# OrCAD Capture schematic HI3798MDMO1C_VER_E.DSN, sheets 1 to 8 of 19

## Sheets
1 SHEET_01
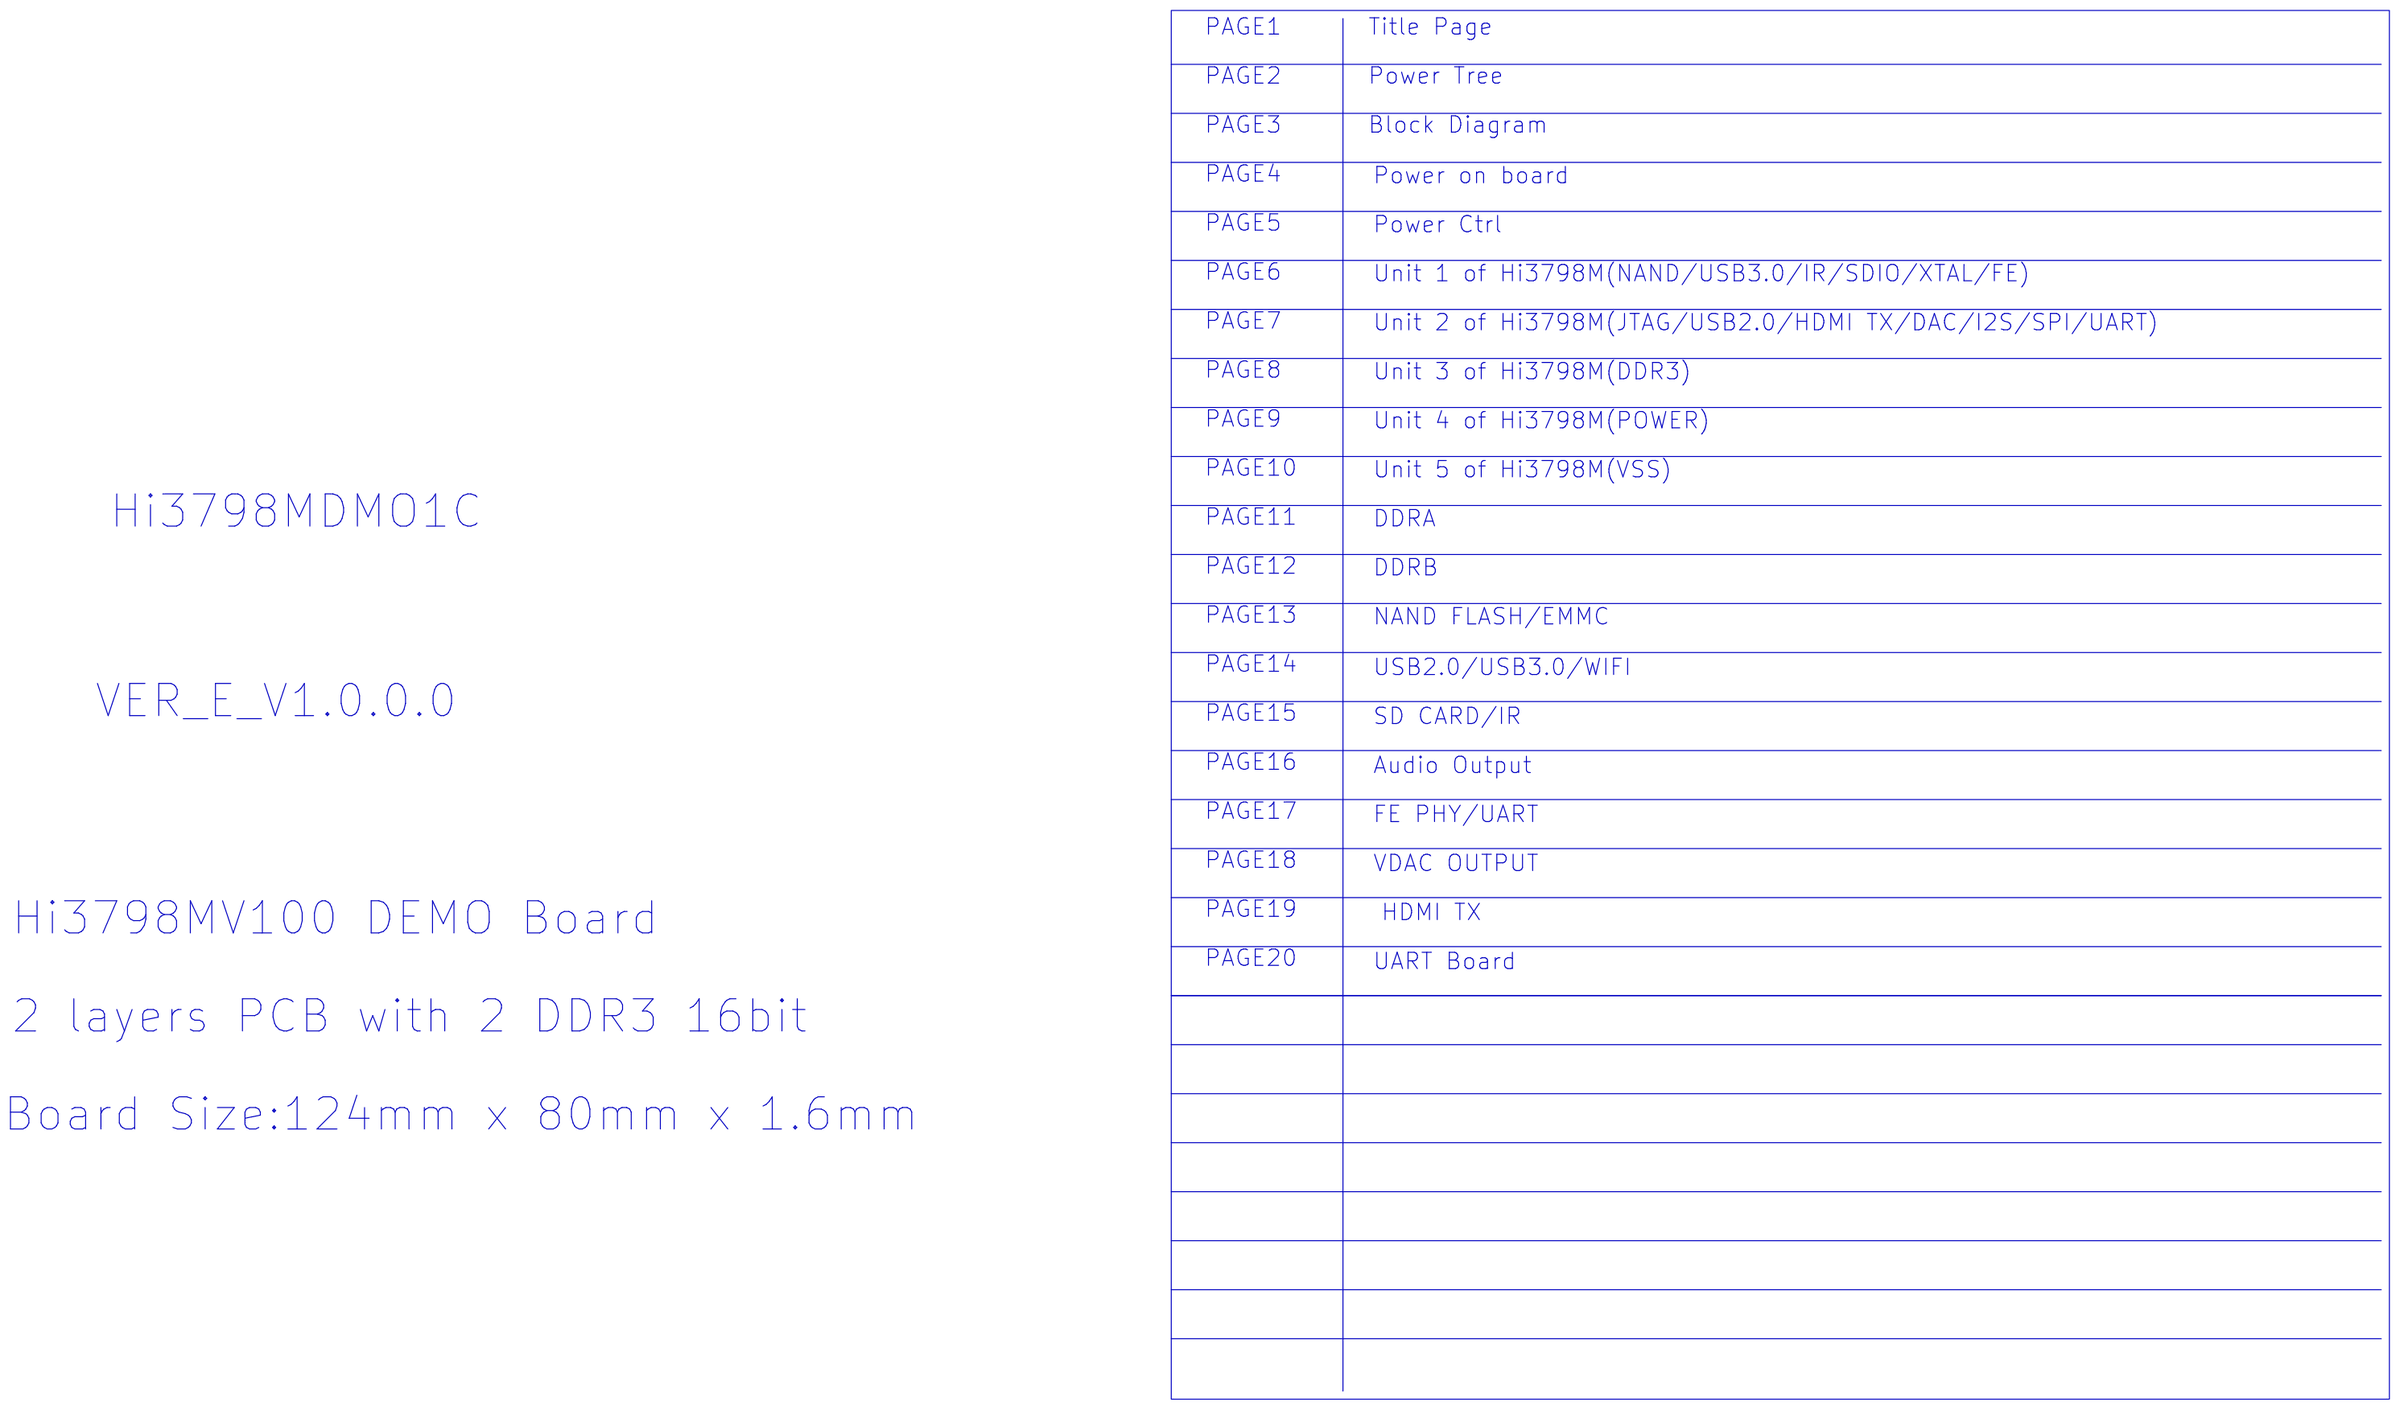
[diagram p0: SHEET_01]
2 SHEET_02
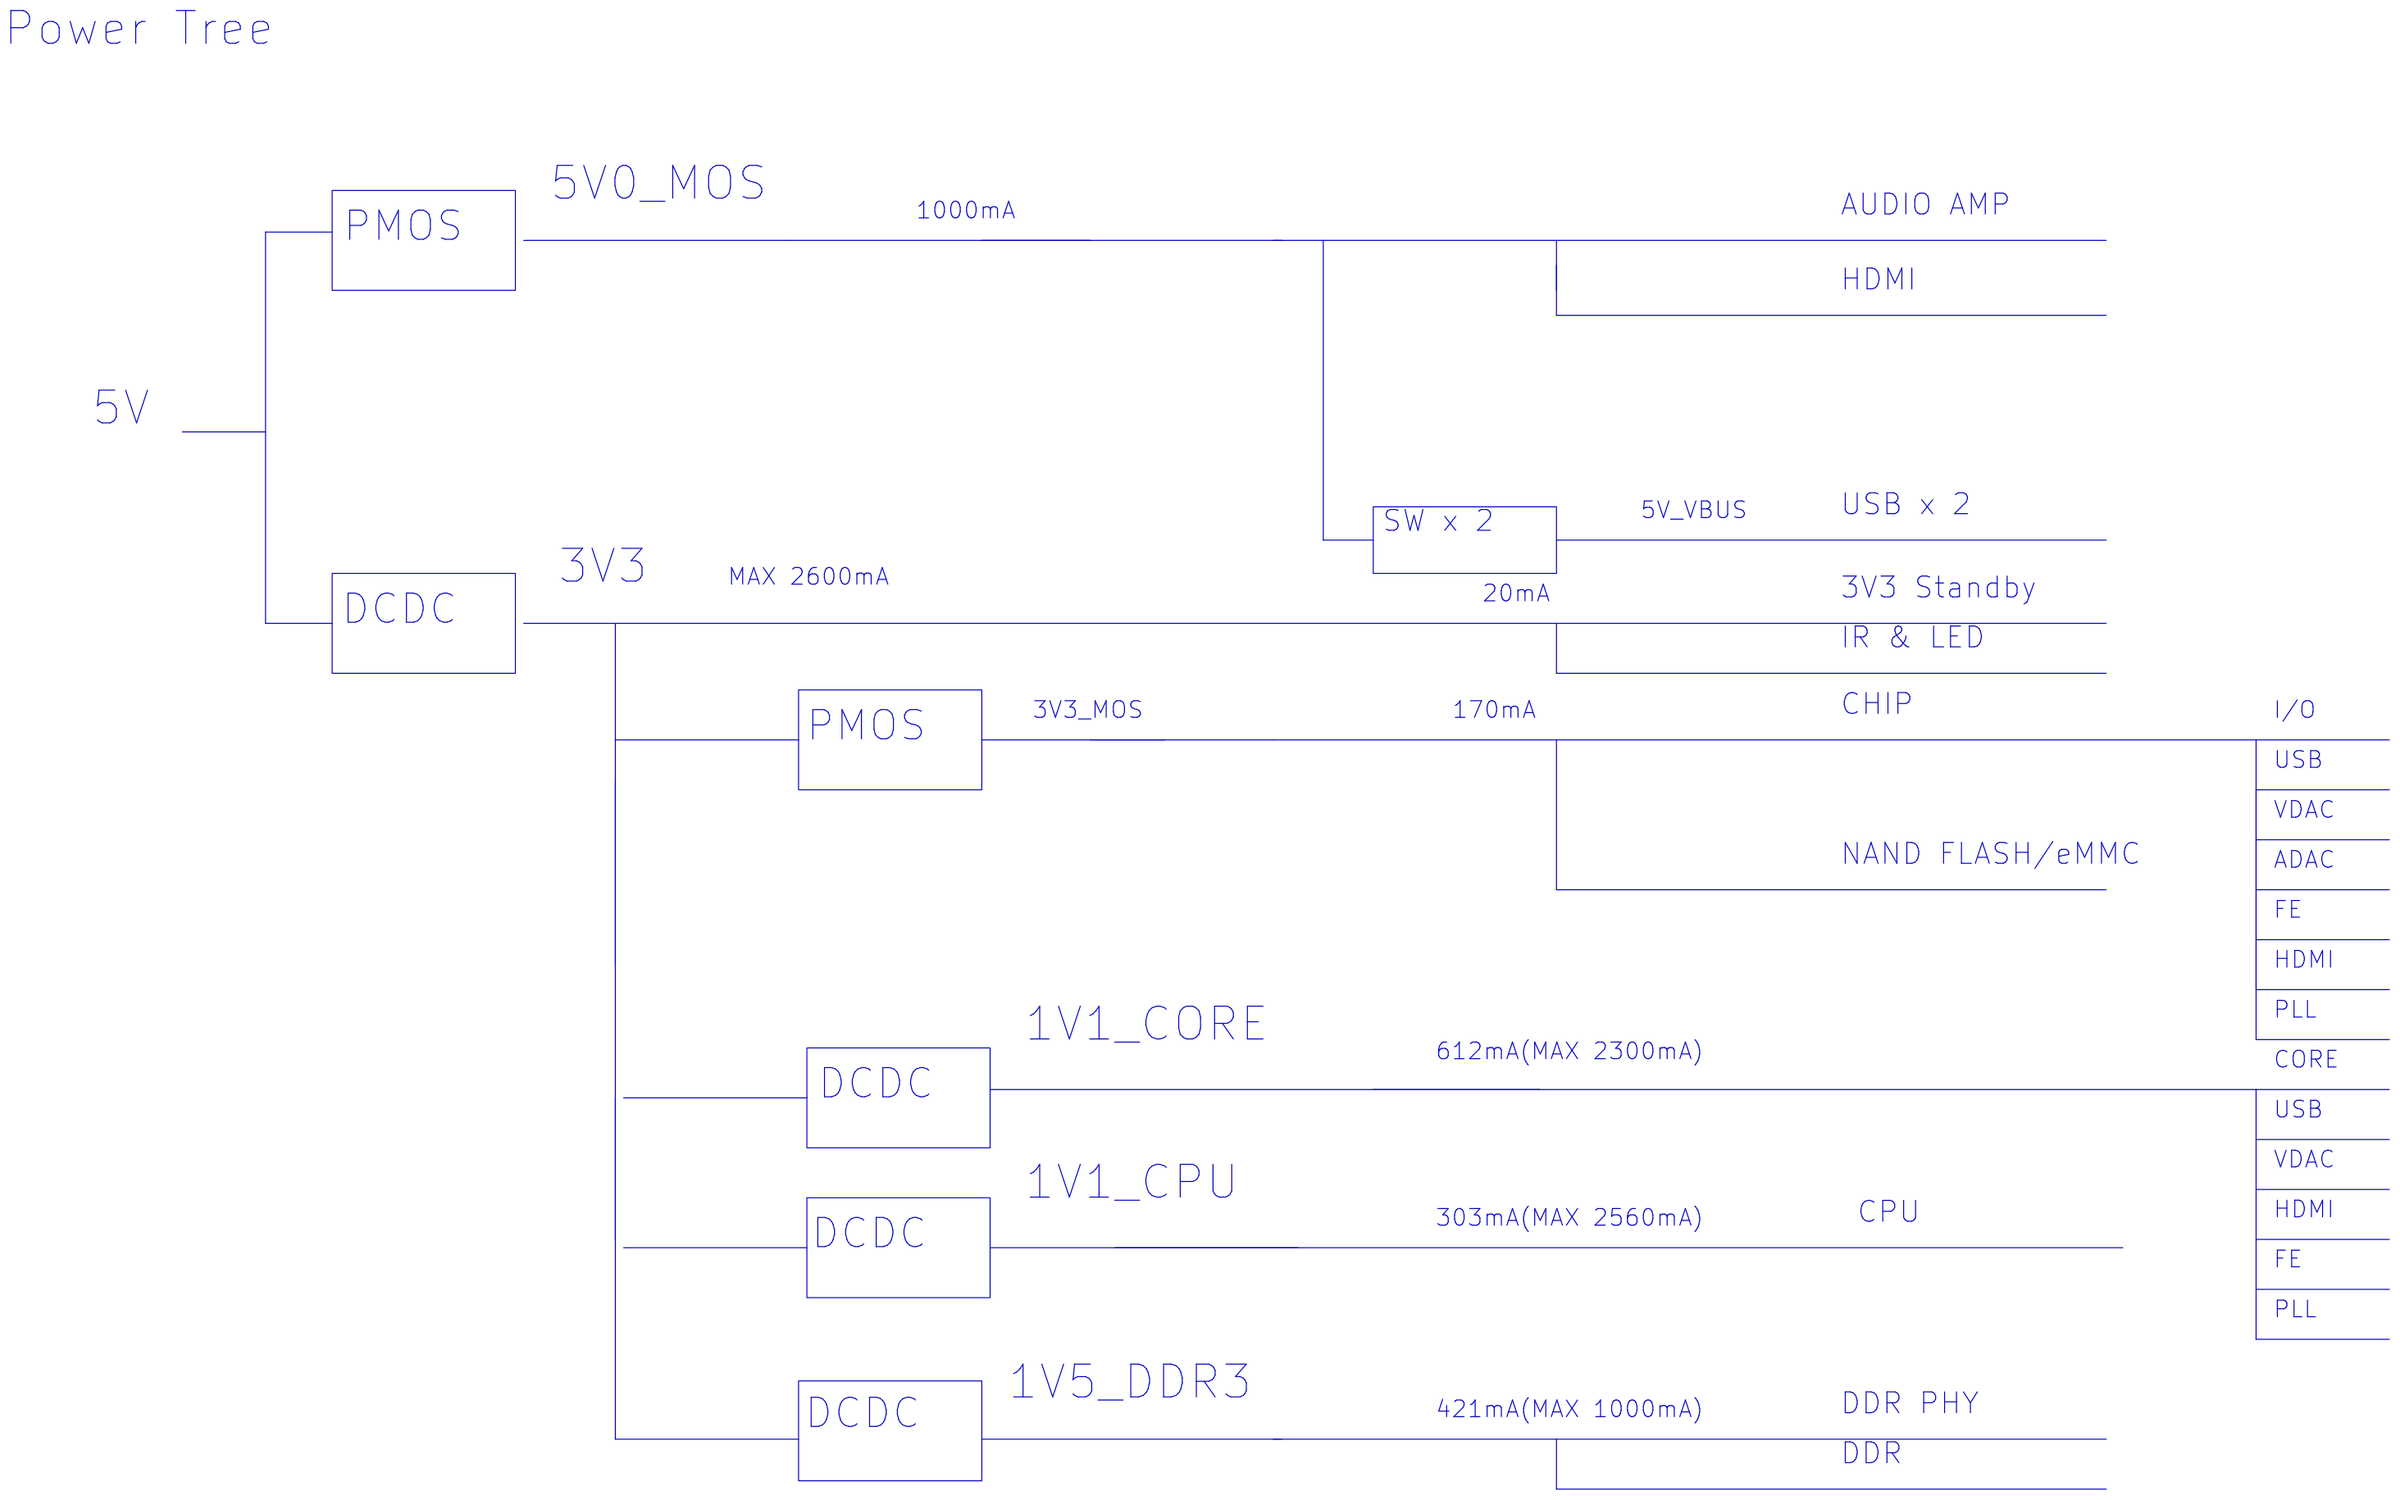
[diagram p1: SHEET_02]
3 SHEET_03: size Custom
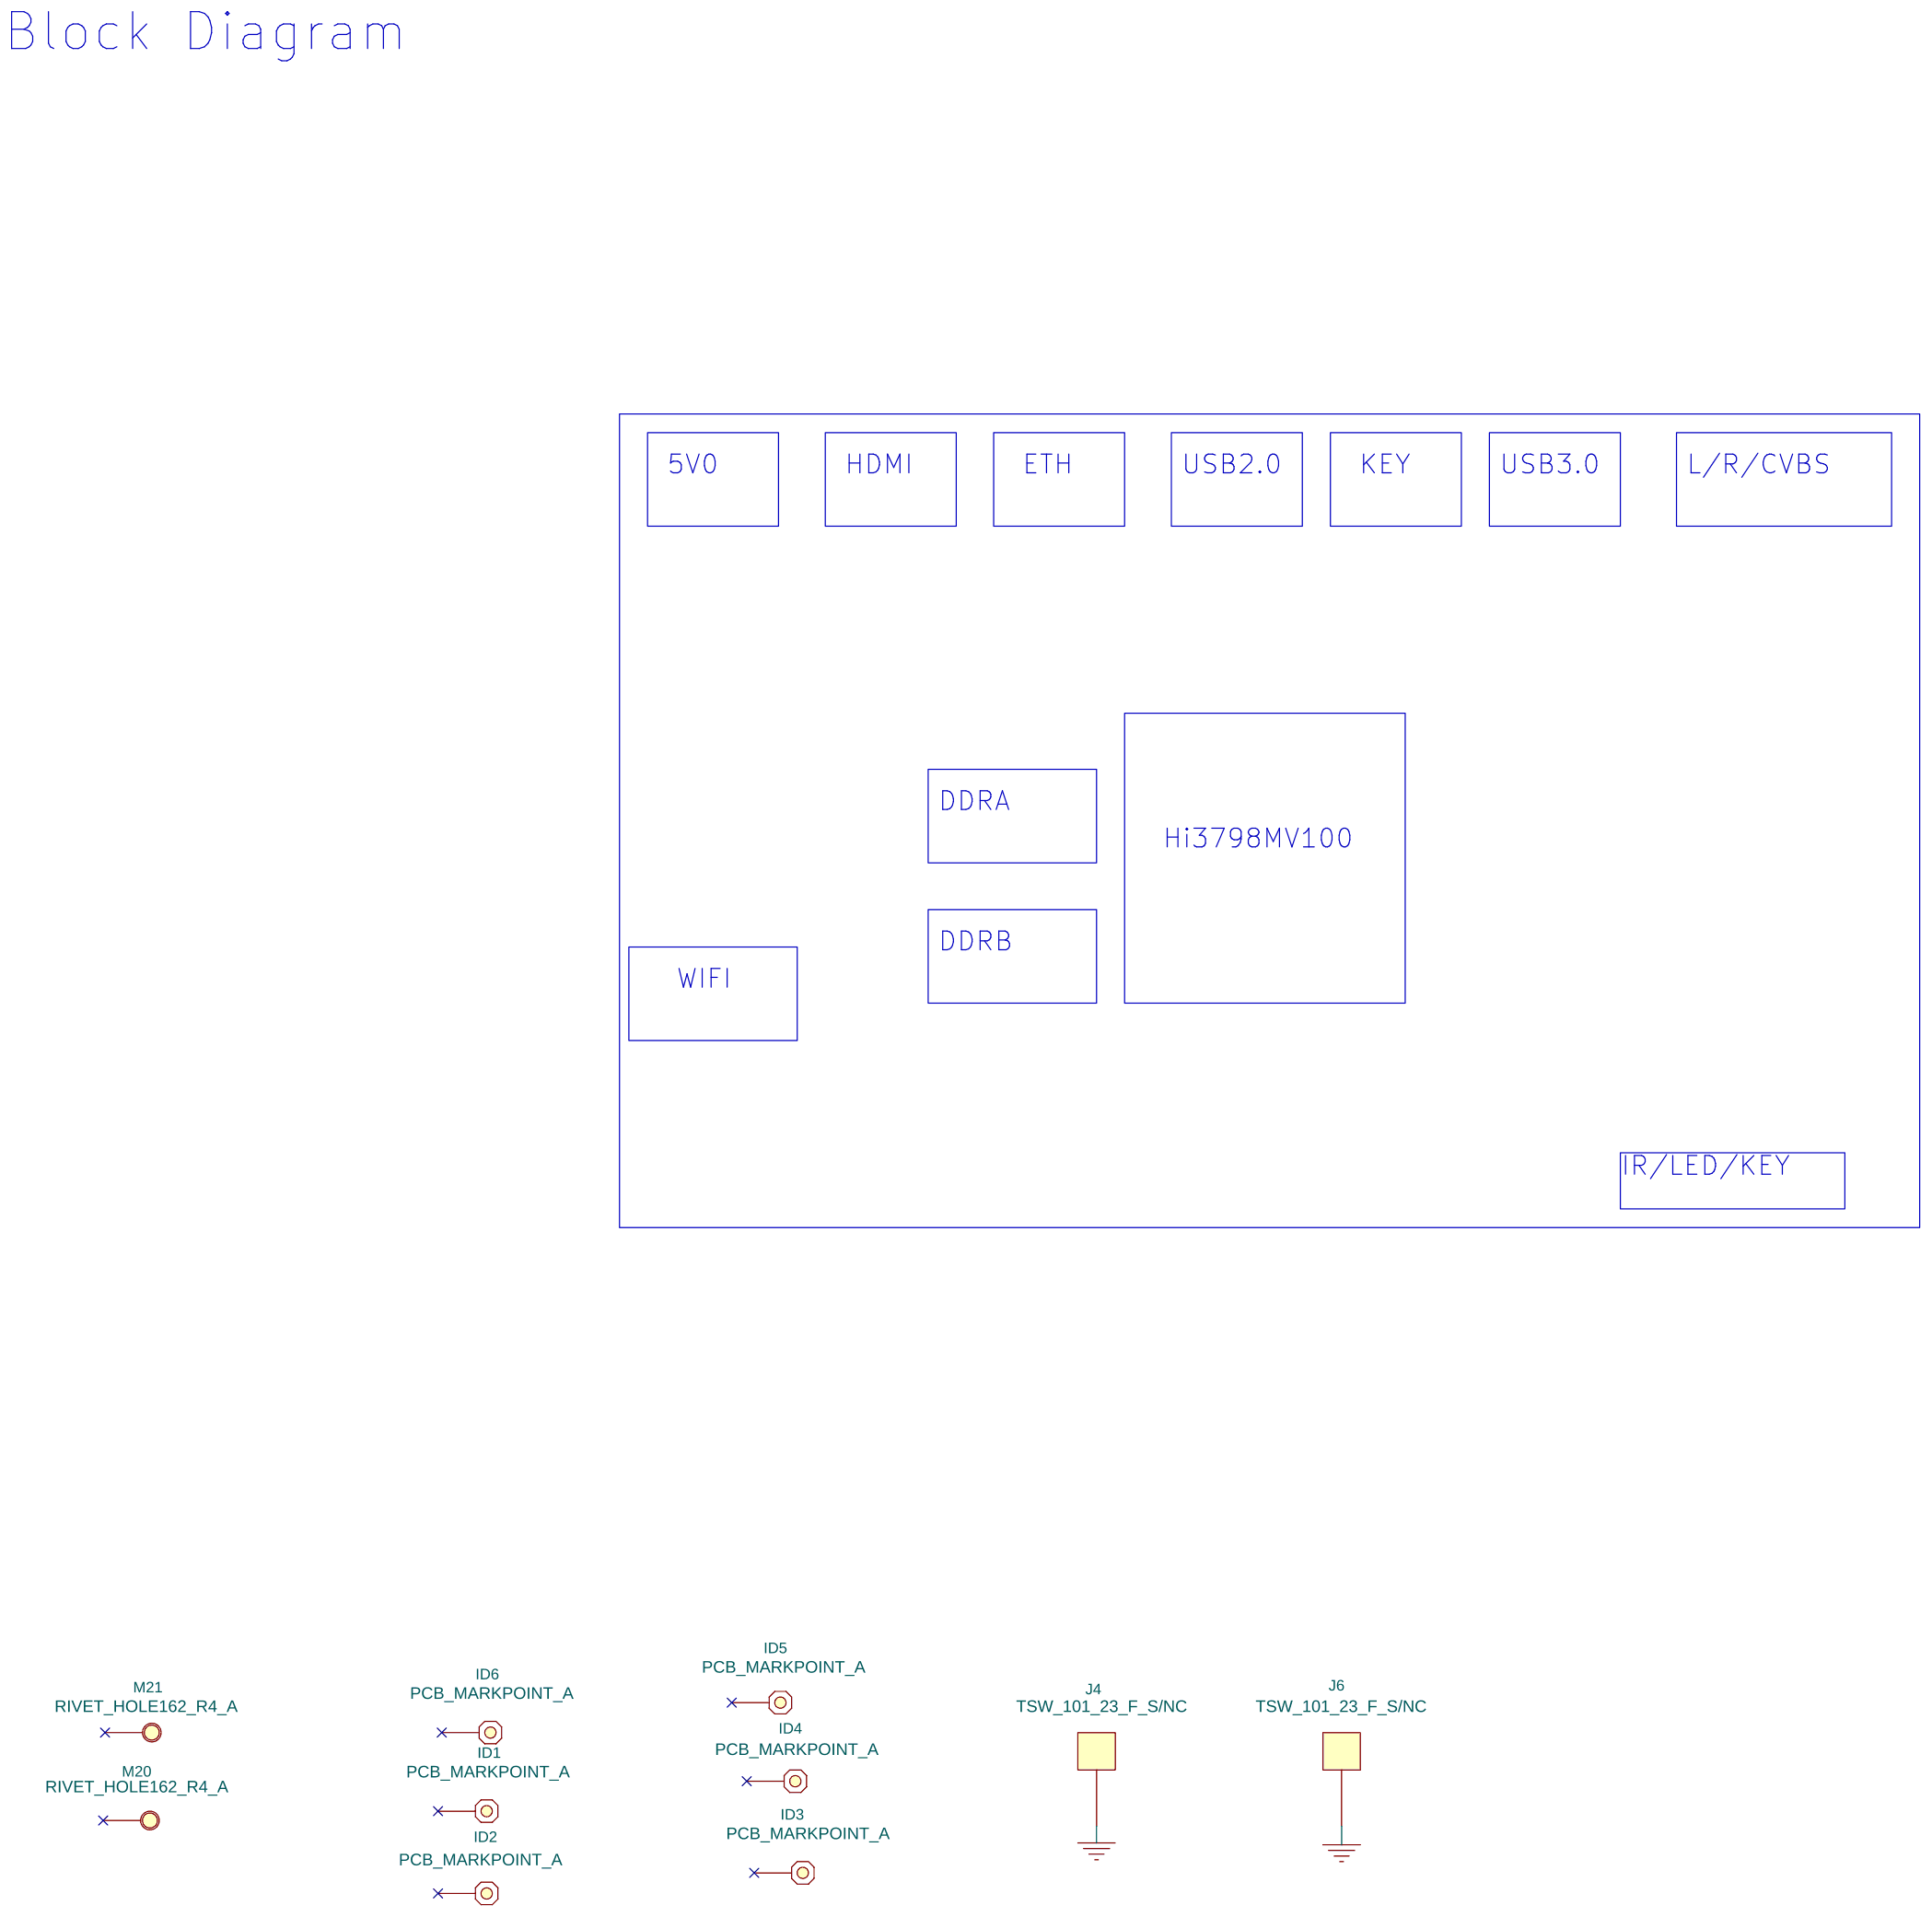
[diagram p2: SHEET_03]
4 SHEET_04: size Custom
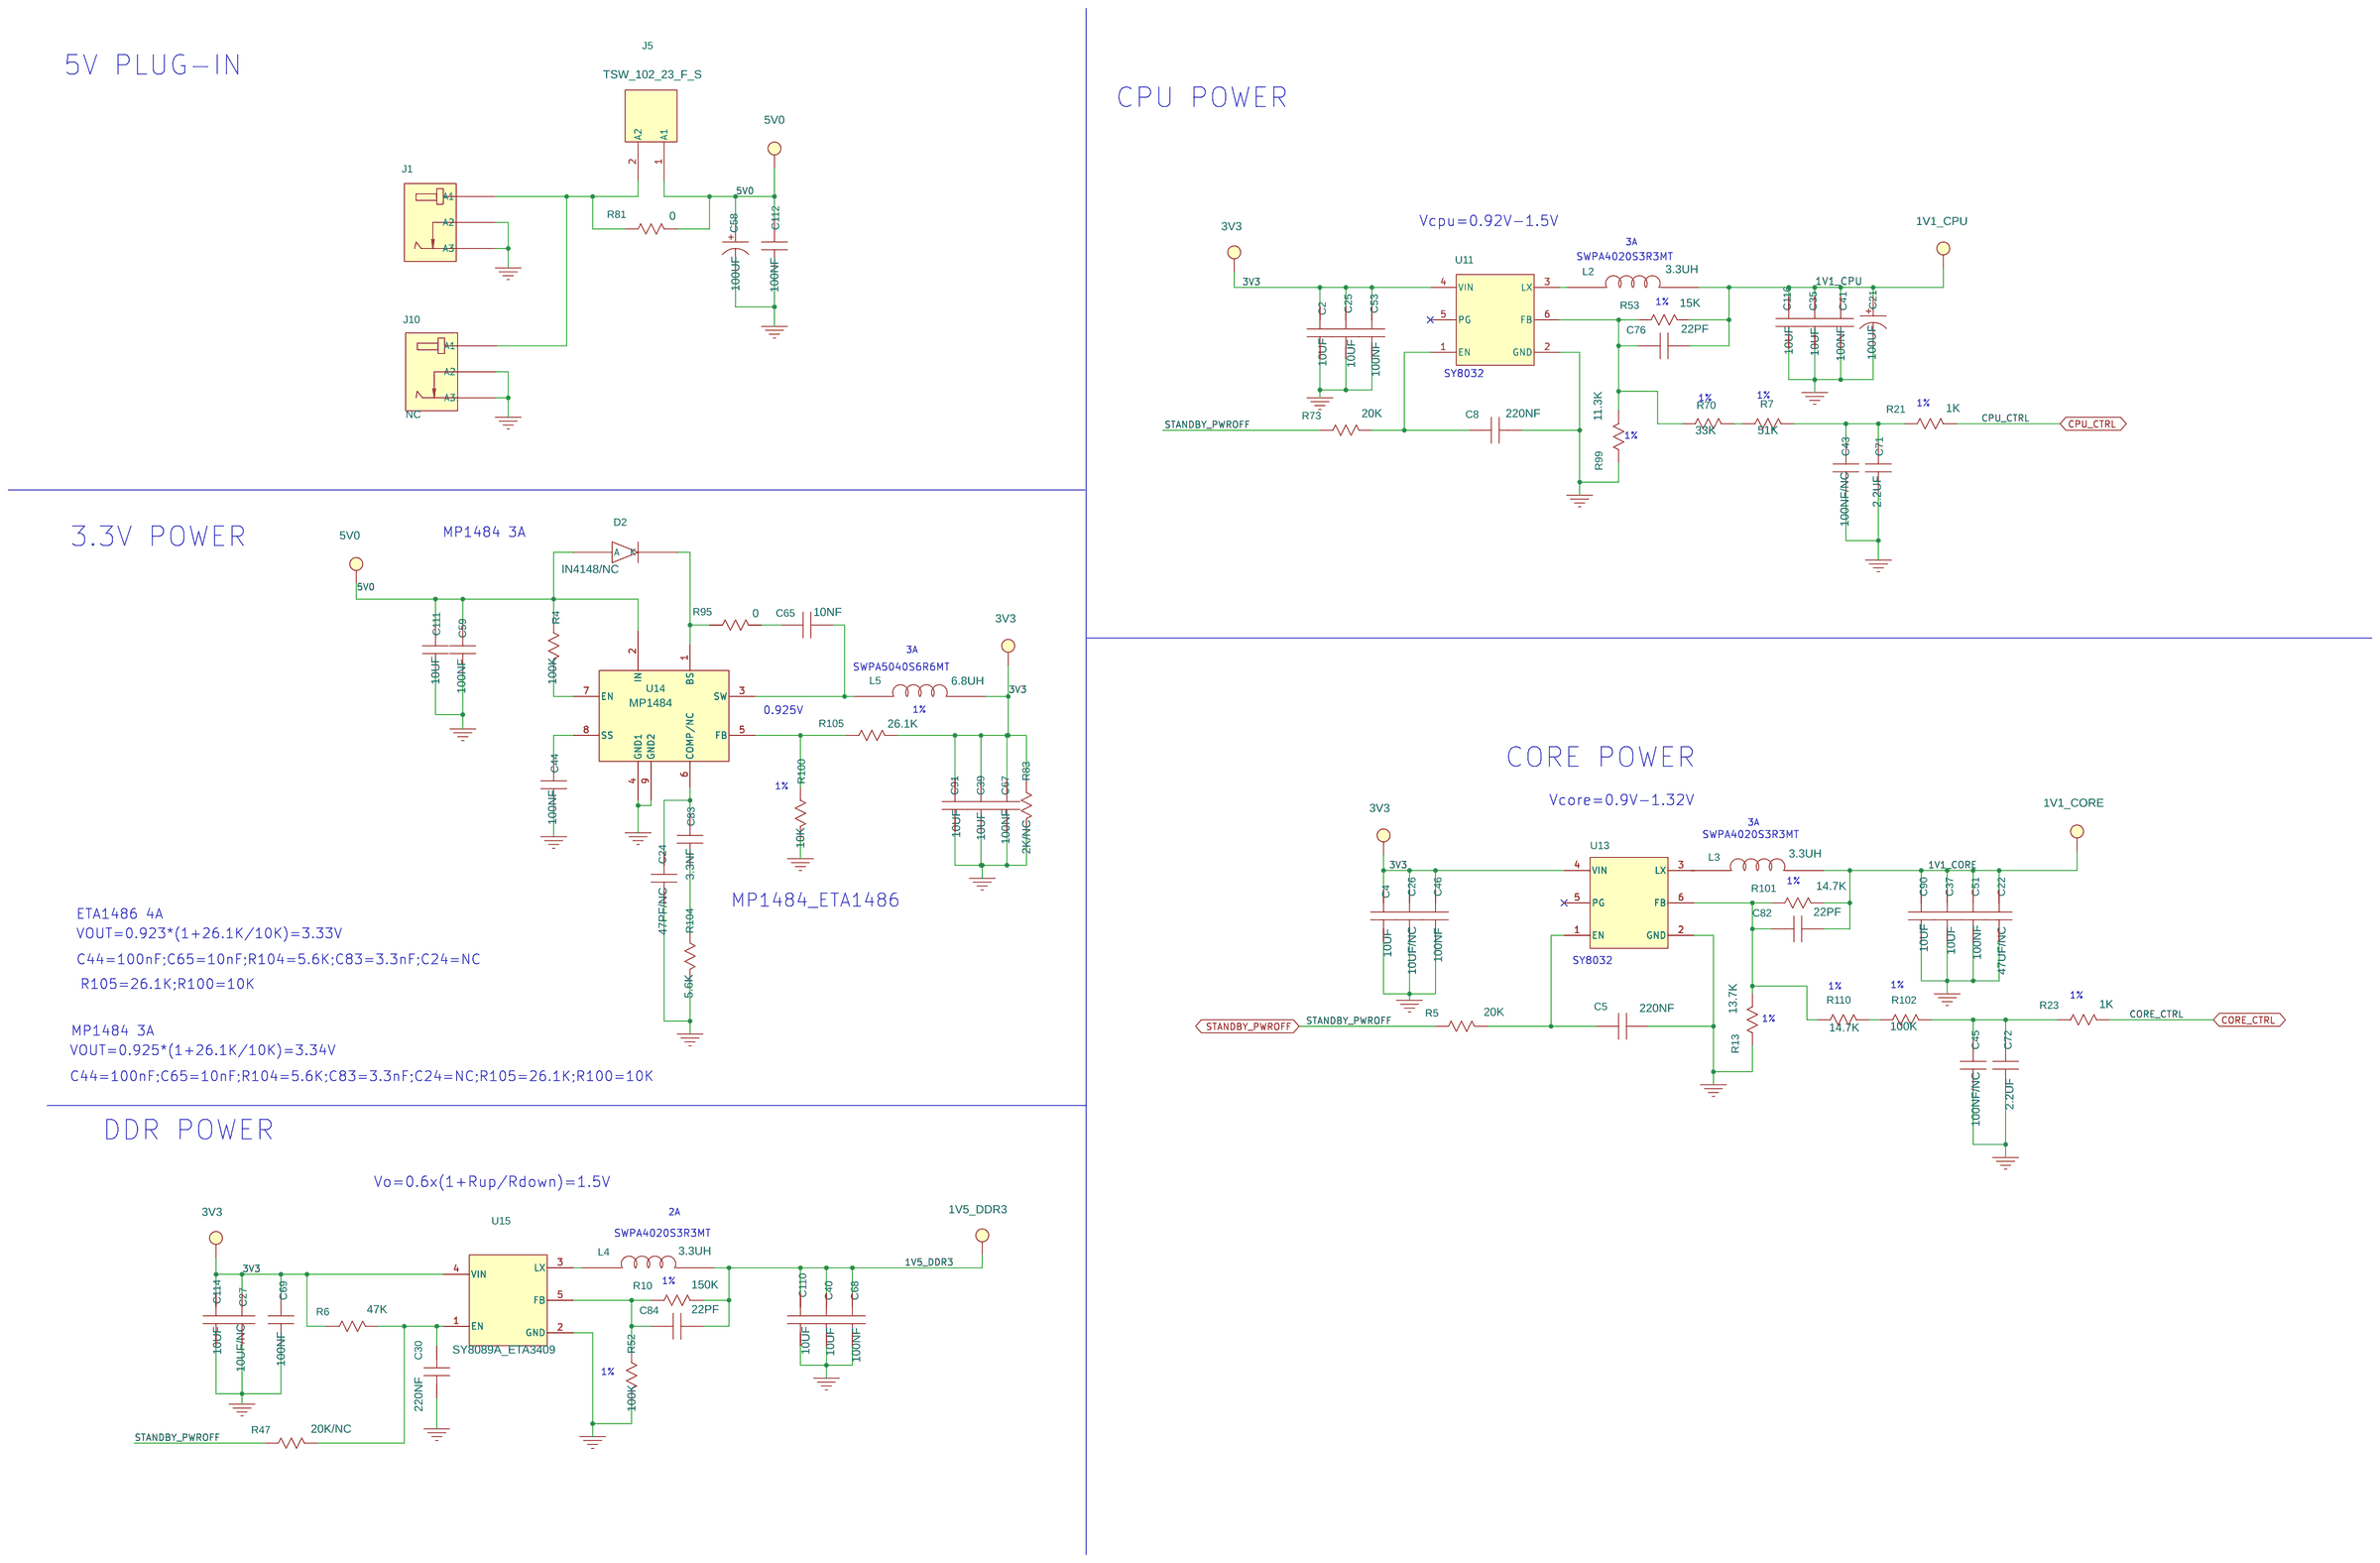
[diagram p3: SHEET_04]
5 SHEET_05: size A
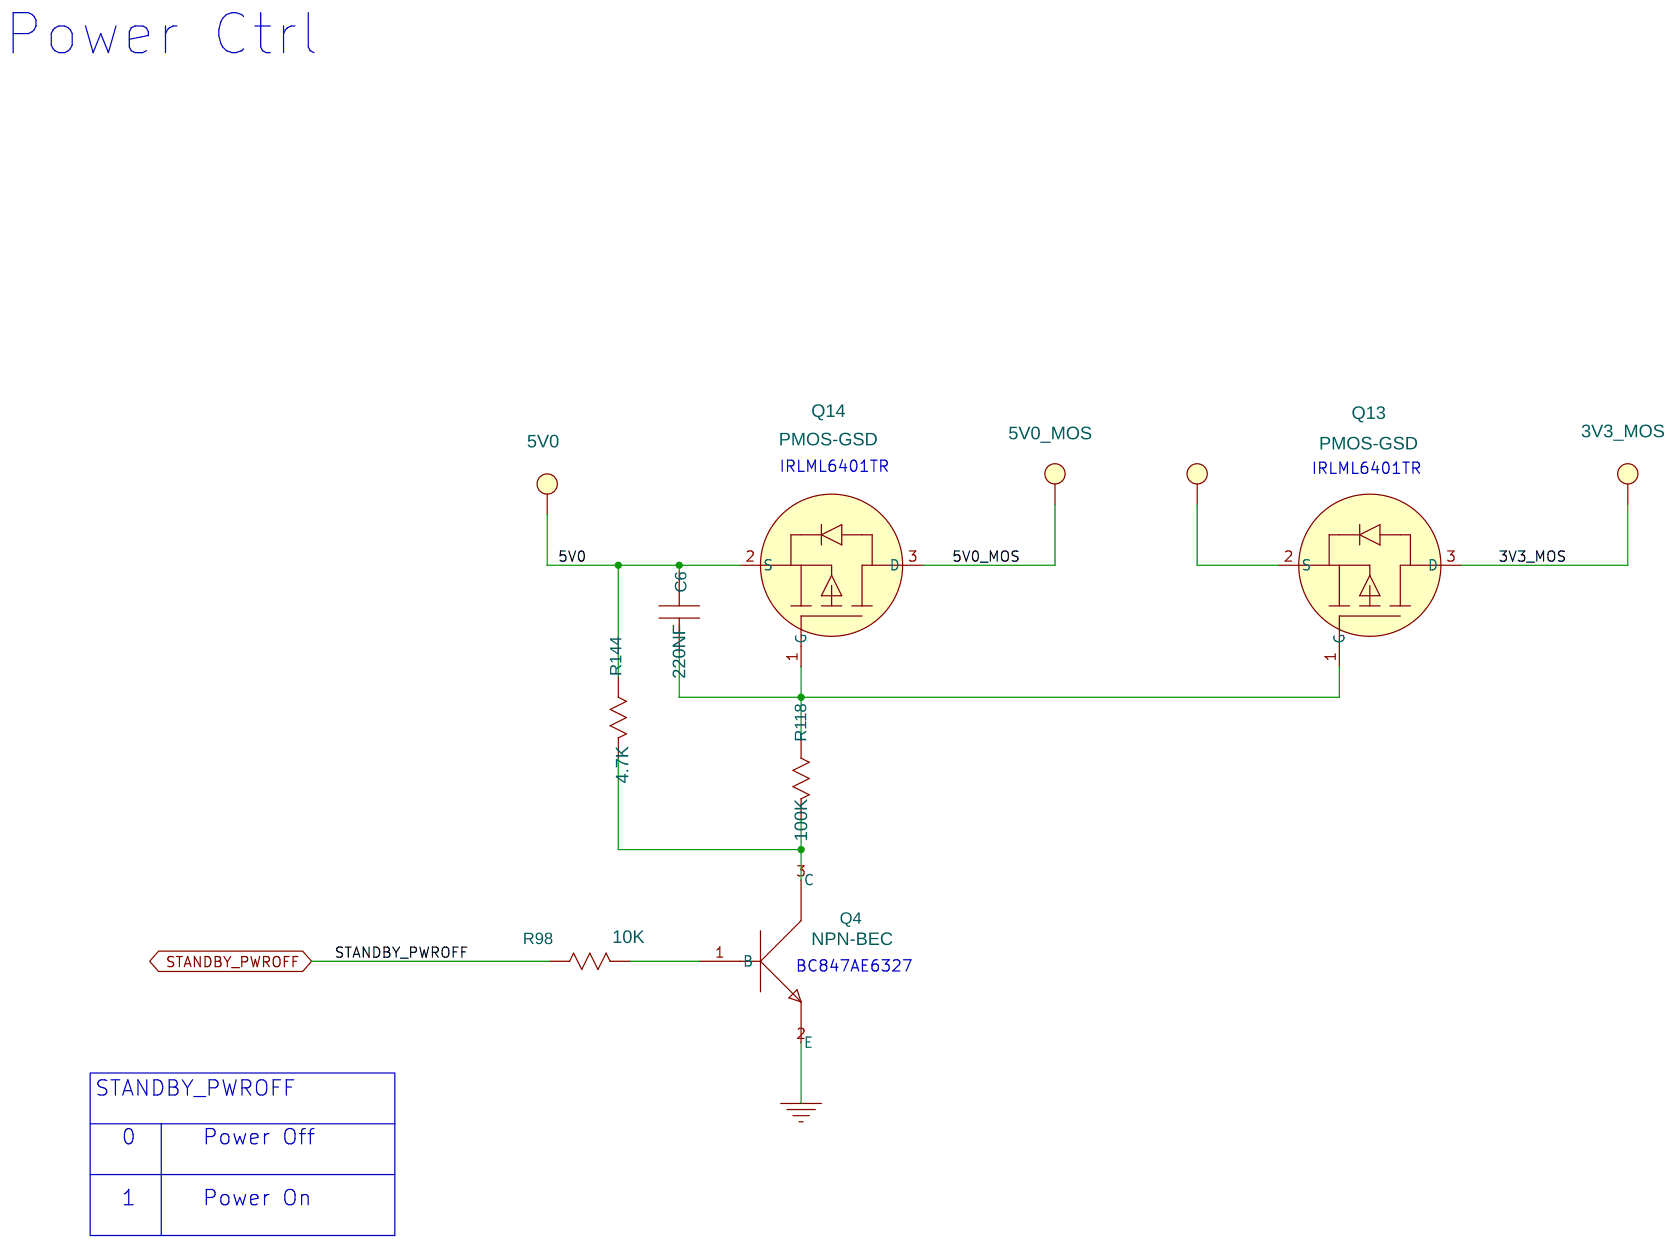
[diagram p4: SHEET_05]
6 SHEET_06: size Custom
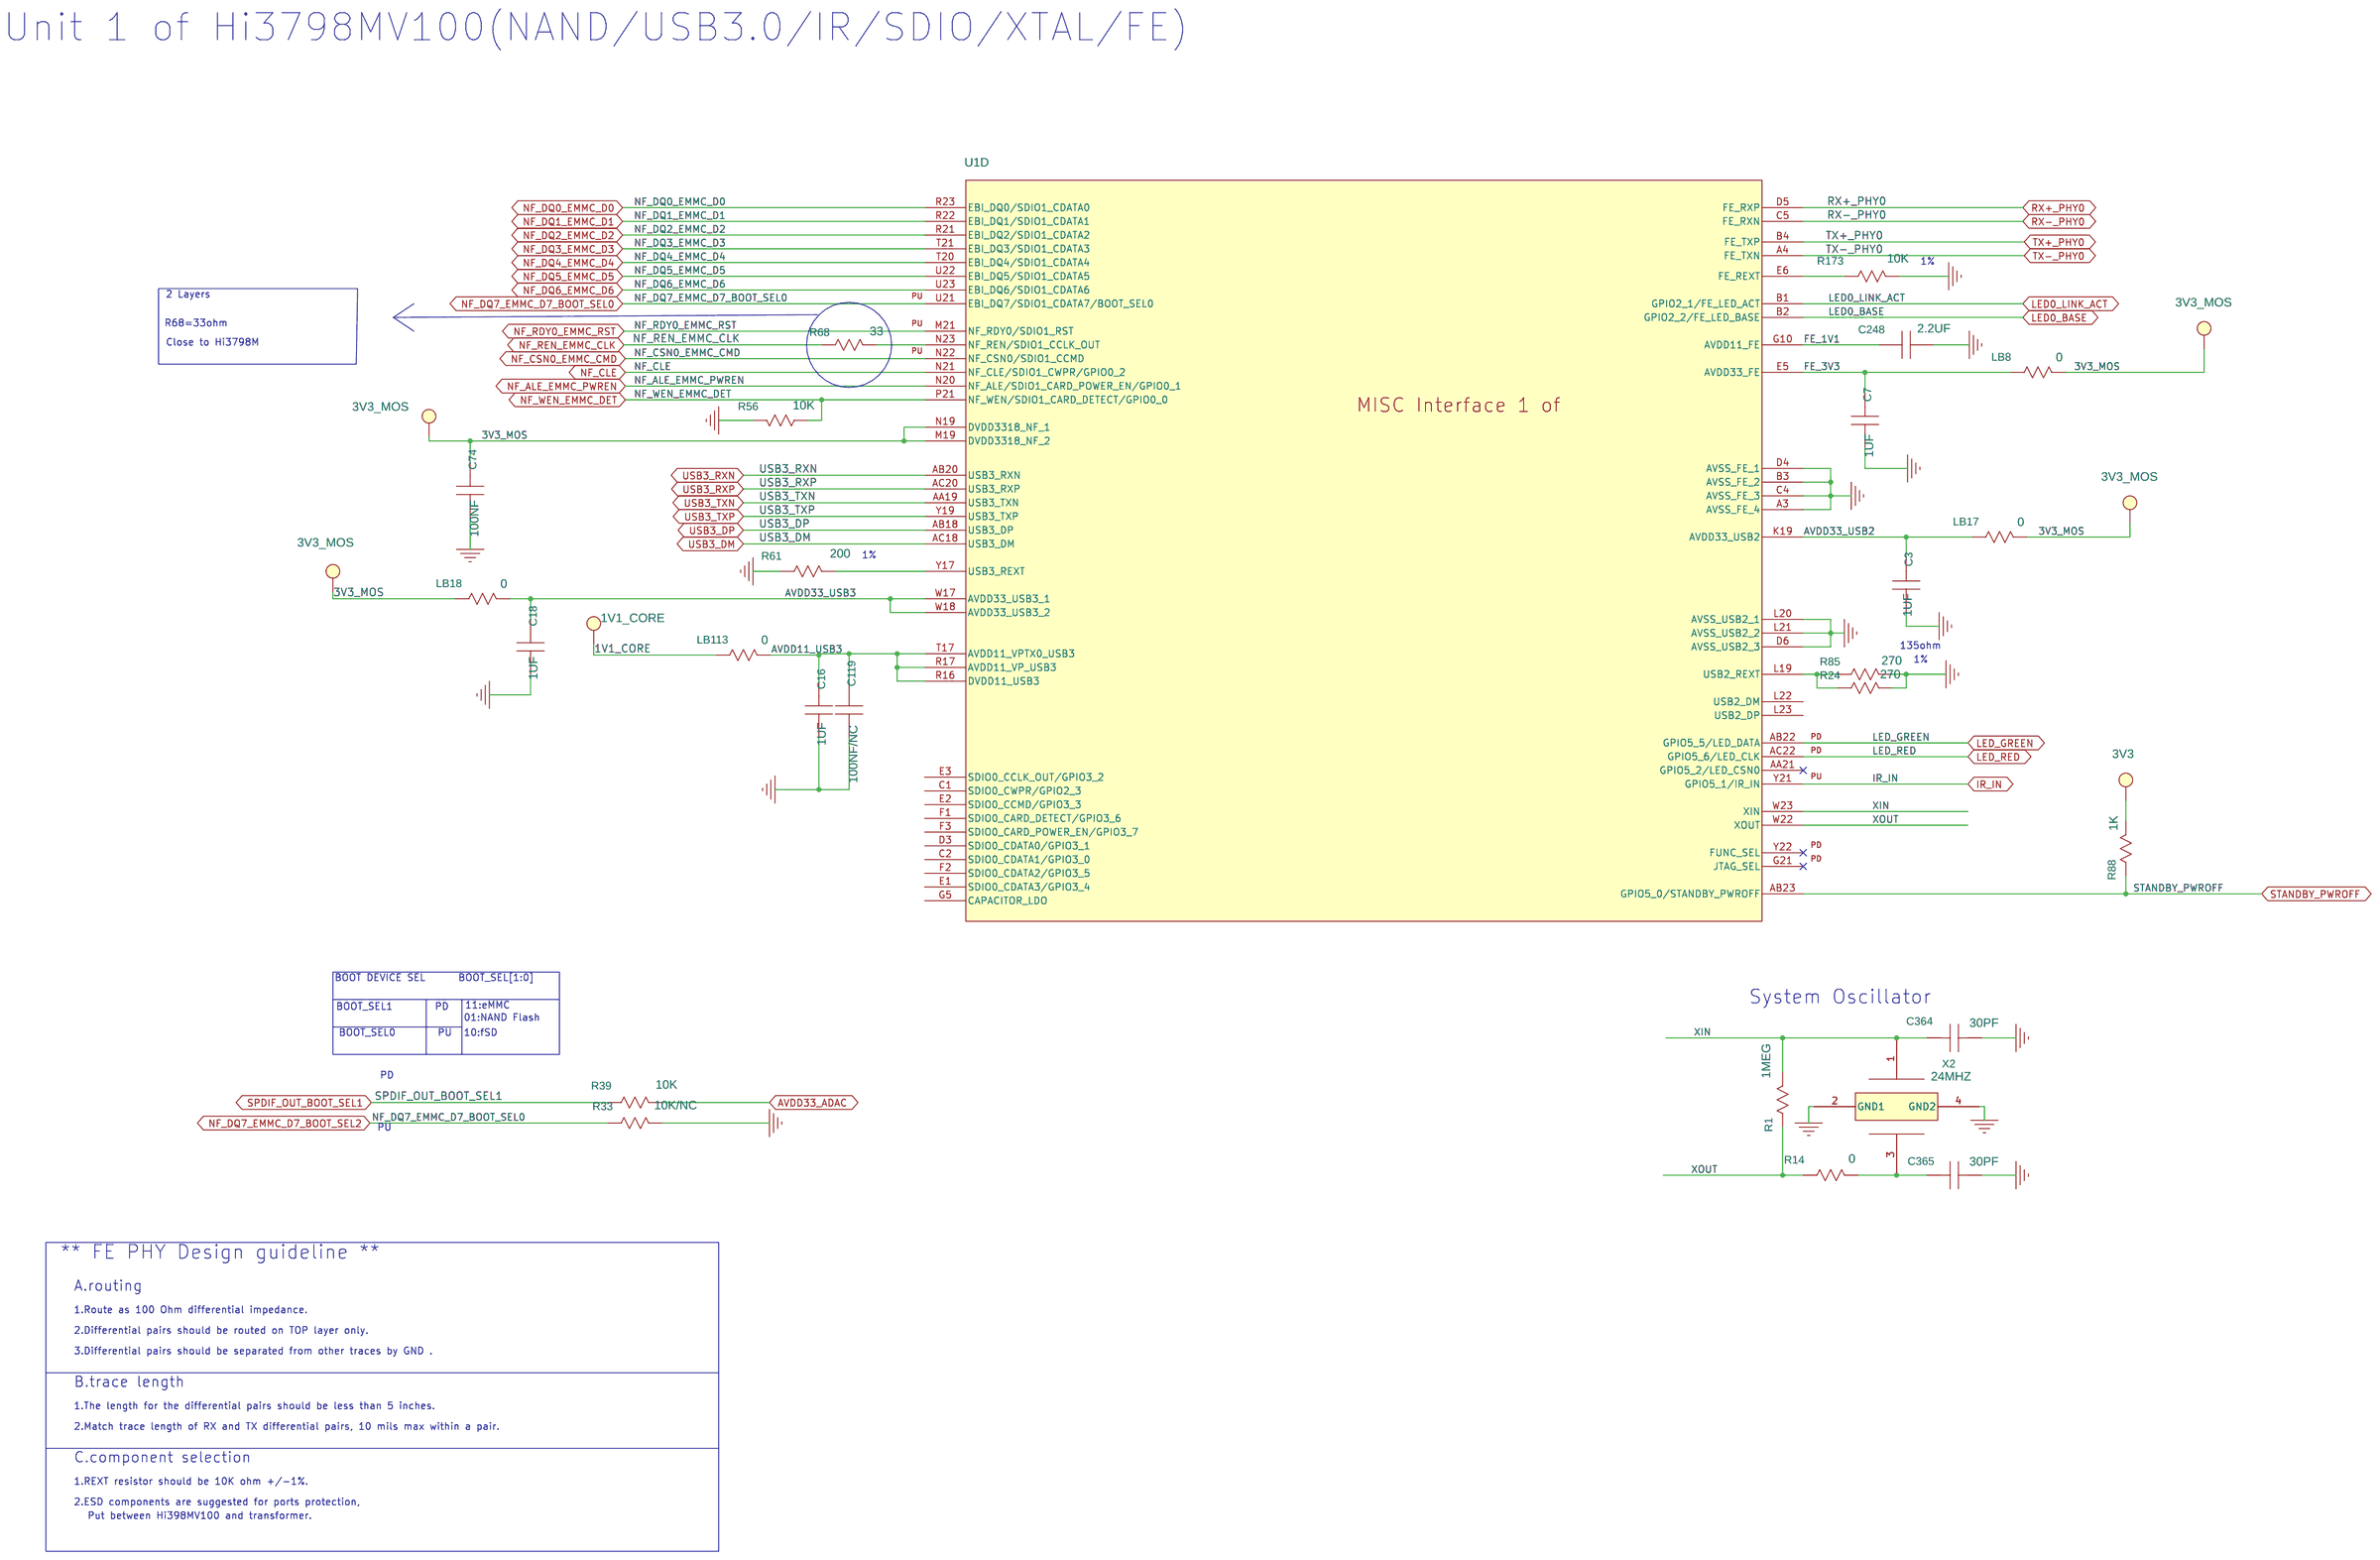
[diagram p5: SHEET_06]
7 SHEET_07: size Custom
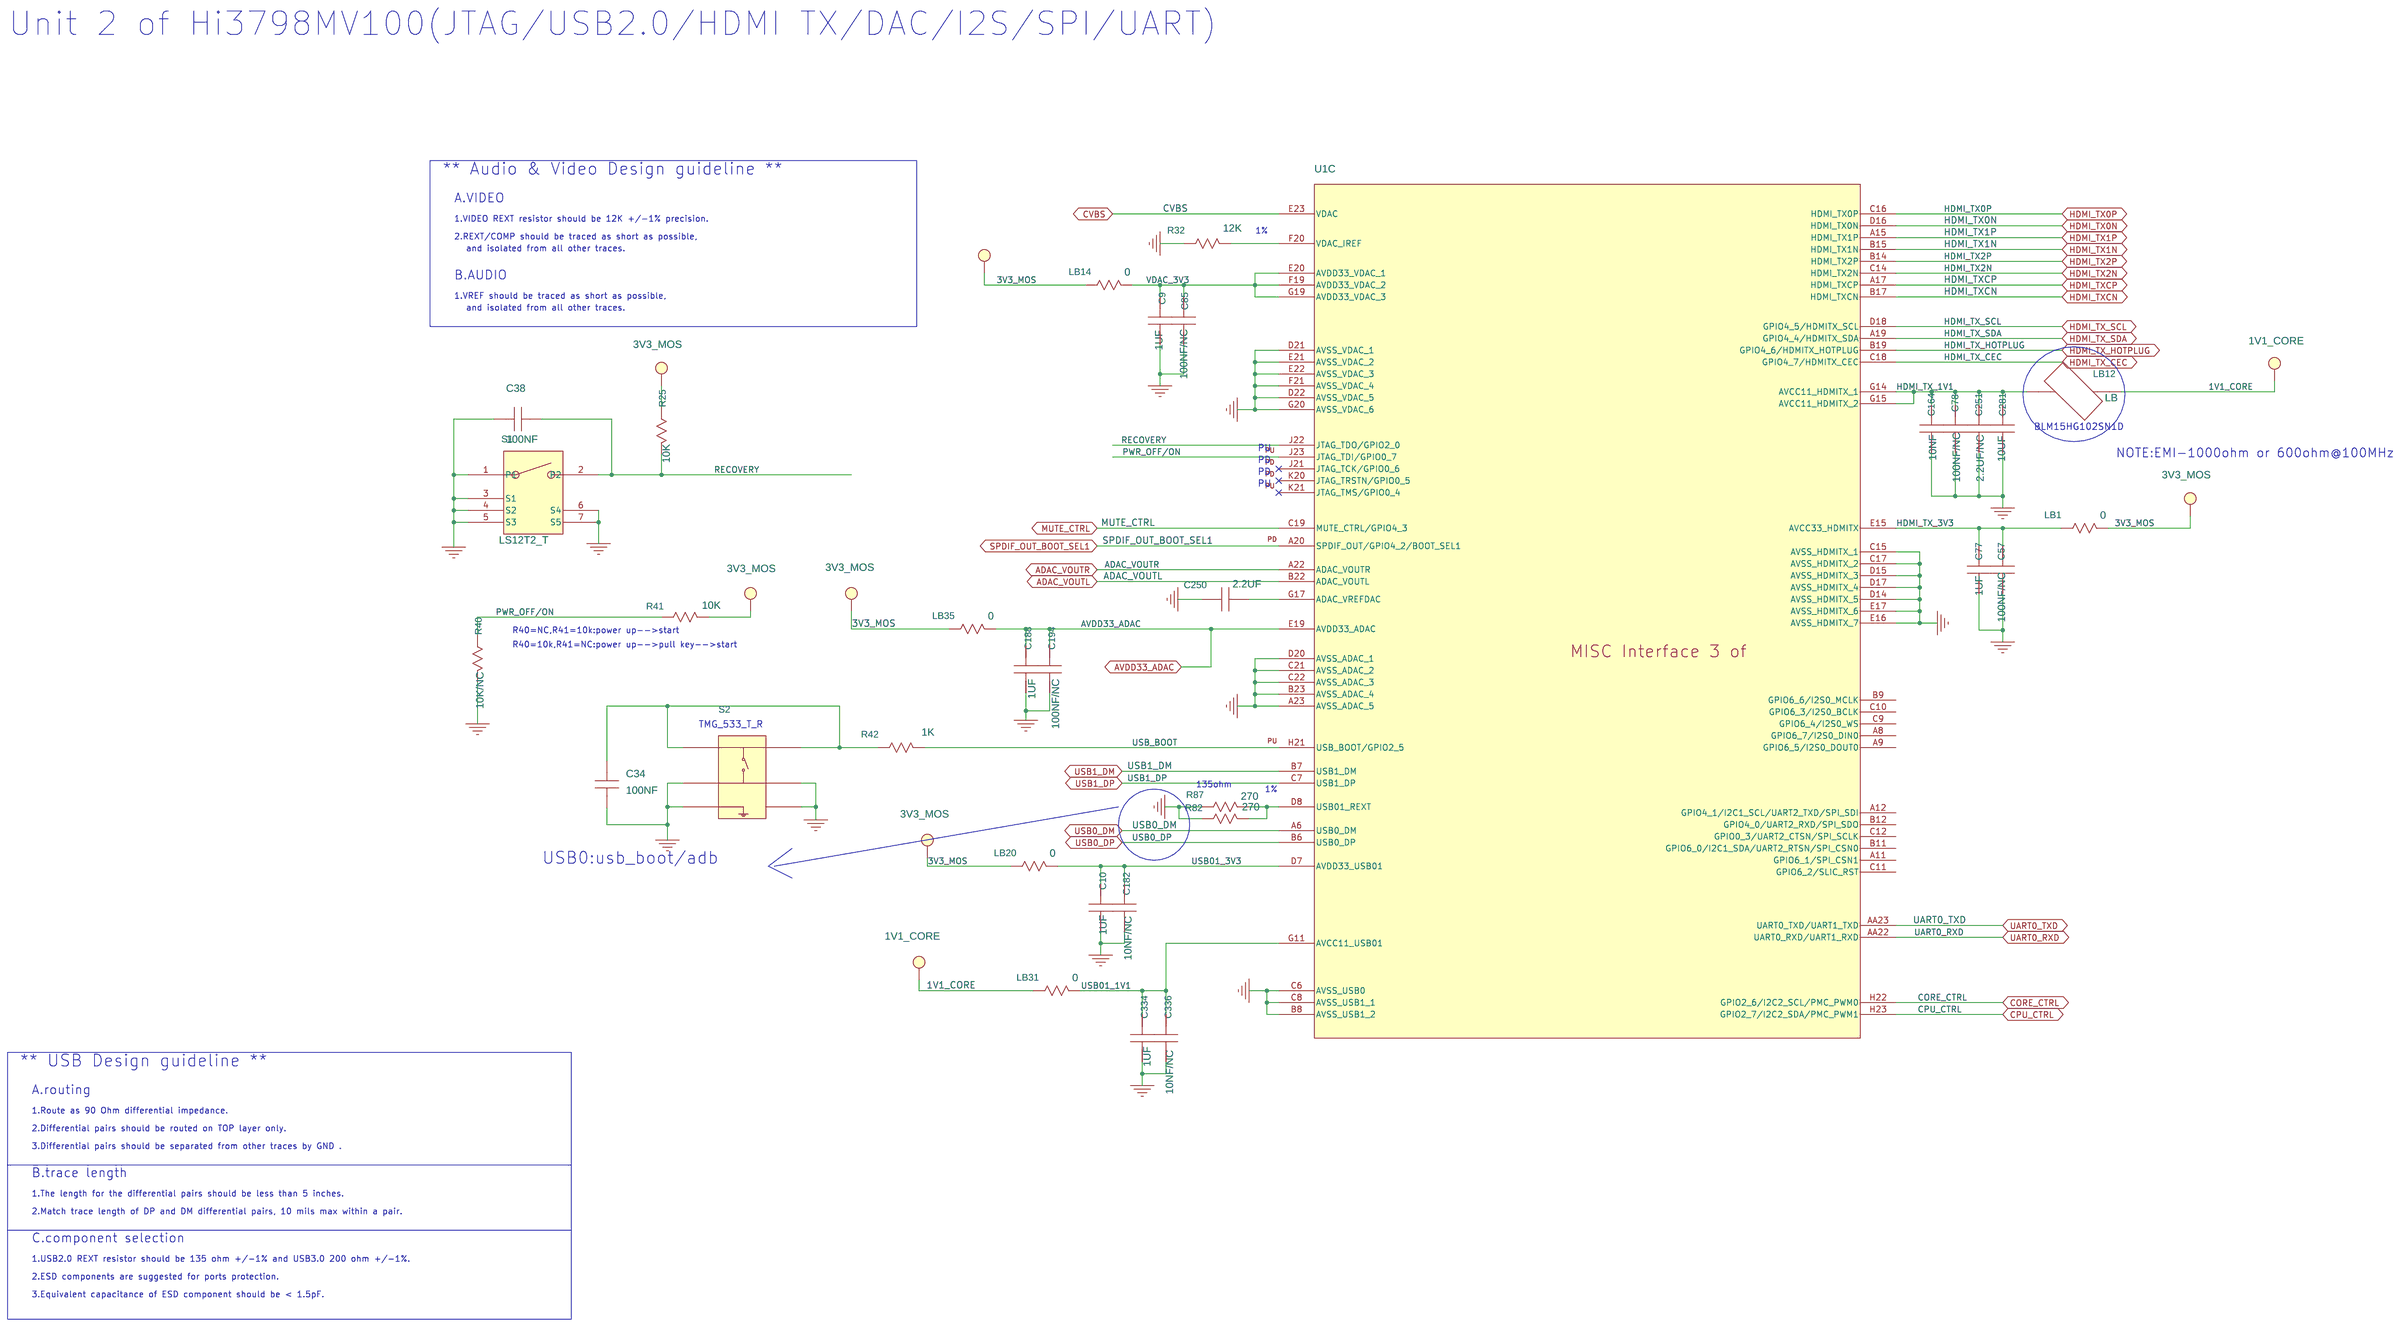
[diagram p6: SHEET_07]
8 SHEET_08: size Custom
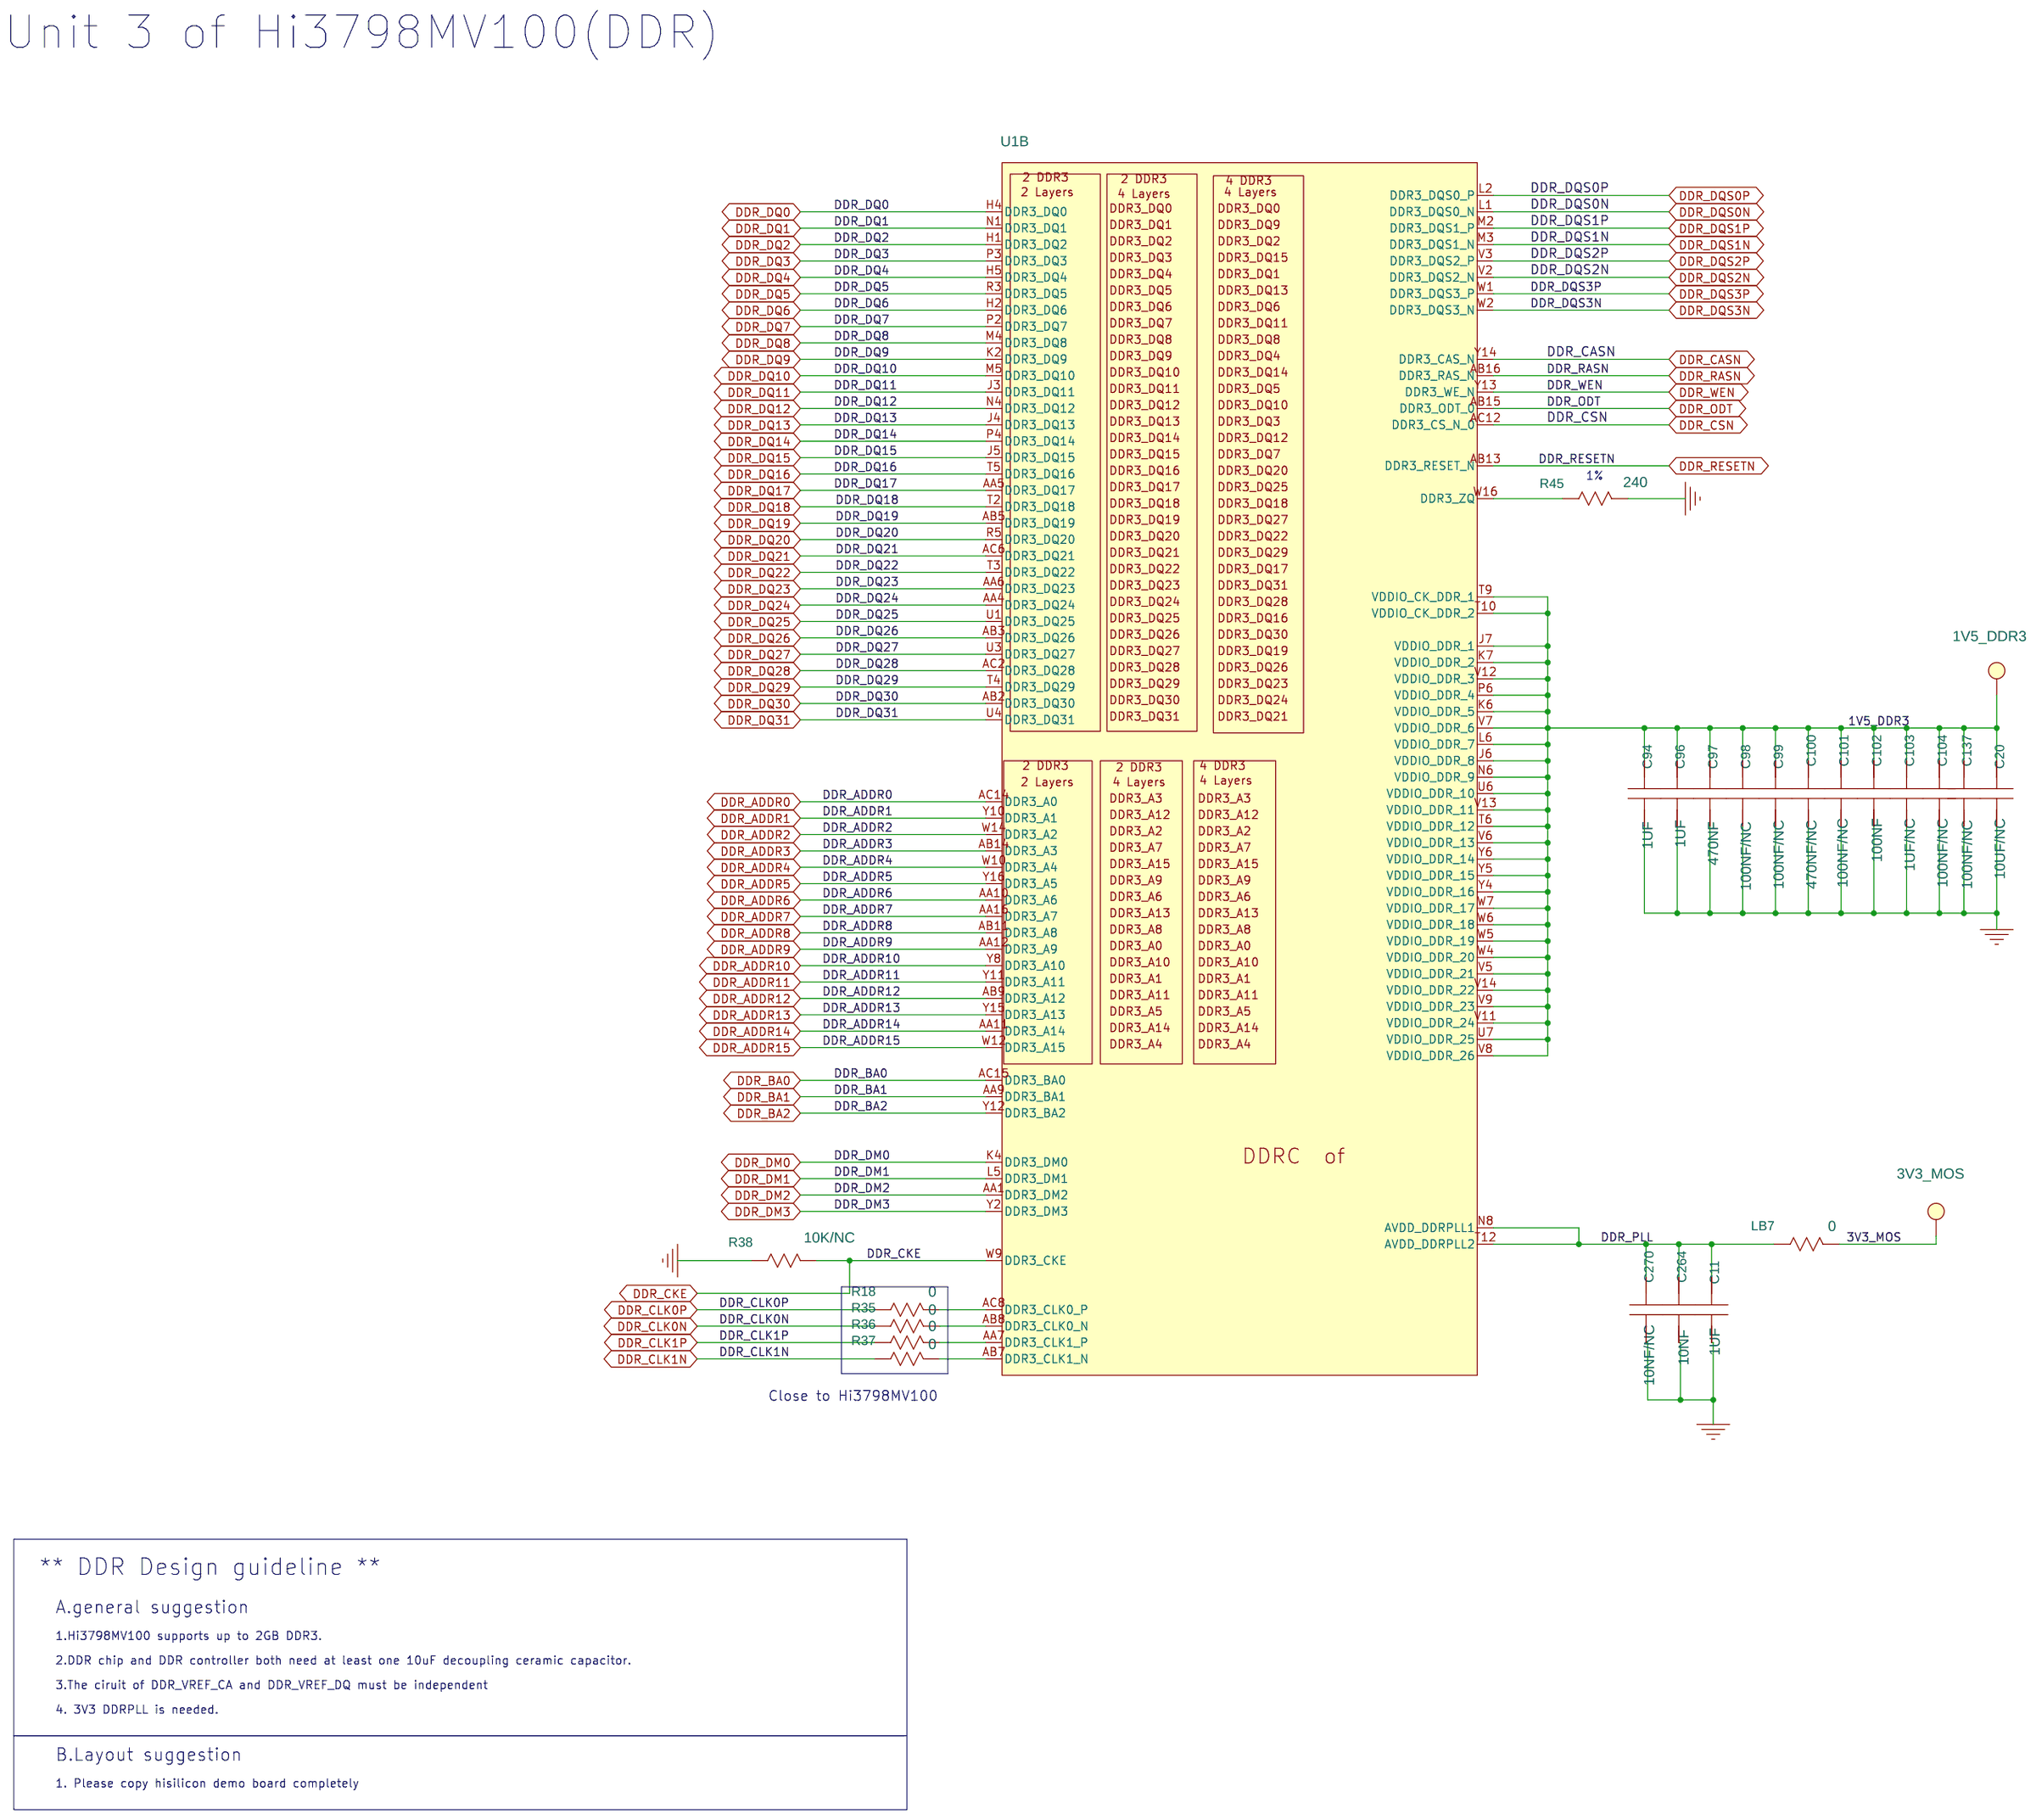
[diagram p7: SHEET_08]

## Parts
sheet SHEET_03
ID1  ID-BOARD  [ID-BOARD]
ID2  ID-BOARD  [ID-BOARD]
ID3  ID-BOARD  [ID-BOARD]
ID4  ID-BOARD  [ID-BOARD]
ID5  ID-BOARD  [ID-BOARD]
ID6  ID-BOARD  [ID-BOARD]
J4  NC  [SIP-1P]
J6  NC  [SIP-1P]
M20  HOLE  [HOLE182-142]
M21  HOLE  [HOLE182-142]
sheet SHEET_04
C2  10UF  [SC0805]
C4  10UF  [SC0805]
C5  220NF  [SC0402]
C8  220NF  [SC0402]
C21  100UF  [SAC6666]
C22  47UF/NC  [SC1206]
C24  47PF/NC  [SC0402]
C25  10UF  [SC0805]
C26  10UF/NC  [SC0805]
C27  10UF/NC  [SC0805]
C30  220NF  [SC0402]
C35  10UF  [SC0603]
C37  10UF  [SC0603]
C39  10UF  [SC0603]
C40  10UF  [SC0603]
C41  100NF  [SC0402]
C43  100NF/NC  [SC0402]
C44  100NF  [SC0402]
C45  100NF/NC  [SC0402]
C46  100NF  [SC0402]
C51  100NF  [SC0402]
C53  100NF  [SC0402]
C58  100UF  [SAC6666]
C59  100NF  [SC0402]
C65  10NF  [SC0402]
C67  100NF  [SC0402]
C68  100NF  [SC0402]
C69  100NF  [SC0402]
C71  2.2UF  [SC0603]
C72  2.2UF  [SC0603]
C76  22PF  [SC0402]
C82  22PF  [SC0402]
C83  3.3NF  [SC0402]
C84  22PF  [SC0402]
C90  10UF  [SC0603]
C91  10UF  [SC0603]
C110  10UF  [SC0603]
C111  10UF  [SC0805]
C112  100NF  [SC0402]
C114  10UF  [SC0805]
C116  10UF  [SC0603]
D2  D_A  [HSOD323A]
J1  PWC3_C  [PWC3-RF-A]
J5  NC  [SIP-2P]
J10  NC  [DC-002]
L2  3.3UH  [SWPA4020S]
L3  3.3UH  [SWPA4020S]
L4  3.3UH  [SWPA4020S]
L5  6.8UH  [SWPA5040S]
R4  100K  [SR0402]
R5  20K  [SR0402]
R6  47K  [SR0402]
R7  51K  [SR0402]
R10  150K  [SR0402]
R13  13.7K  [SR0402]
R21  1K  [SR0402]
R23  1K  [SR0402]
R47  20K/NC  [SR0402]
R52  100K  [SR0402]
R53  15K  [SR0402]
R70  33K  [SR0402]
R73  20K  [SR0402]
R81  0  [SR1206]
R83  2K/NC  [SR0805]
R95  0  [SR0402]
R99  11.3K  [SR0402]
R100  10K  [SR0402]
R101  14.7K  [SR0402]
R102  100K  [SR0402]
R104  5.6K  [SR0402]
R105  26.1K  [SR0402]
R110  14.7K  [SR0402]
U11  SY8032  [SOT23_6]
U13  SY8032  [SOT23_6]
U14  MP1484  [SOIC8N]
U15  SY8009A  [SOT23_5]
sheet SHEET_05
C6  220NF  [SC0603]
Q4  NPN-BEC  [SOT23]
Q13  PMOS-GSD  [SOT23]
Q14  PMOS-GSD  [SOT23]
R98  10K  [SR0402]
R118  100K  [SR0402]
R144  4.7K  [SR0402]
sheet SHEET_06
C3  1UF  [SC0603]
C7  1UF  [SC0603]
C16  1UF  [SC0603]
C18  1UF  [SC0603]
C74  100NF  [SC0402]
C119  100NF/NC  [SC0402]
C248  2.2UF  [HSC0402]
C364  30PF  [SC0402]
C365  30PF  [SC0402]
LB8  0  [SL0402]
LB17  0  [SL0603]
LB18  0  [SL0402]
LB113  0  [SL0402]
R1  1MEG  [SR0603]
R14  0  [SR0402]
R24  270  [SR0402]
R33  10K/NC  [SR0402]
R39  10K  [SR0402]
R56  10K  [SR0402]
R61  200  [SR0402]
R68  33  [SR0402]
R85  270  [SR0402]
R88  1K  [SR0402]
R173  10K  [SR0402]
X2  24MHZ  [X288]
sheet SHEET_07
C9  1UF  [SC0603]
C10  1UF  [SC0603]
C34  100NF  [SC0402]
C38  100NF  [SC0402]
C57  100NF/NC  [SC0402]
C77  1UF  [SC0402]
C78  100NF/NC  [SC0402]
C85  100NF/NC  [SC0402]
C164  10NF  [SC0402]
C182  10NF/NC  [SC0402]
C188  1UF  [SC0603]
C194  100NF/NC  [SC0402]
C250  2.2UF  [HSC0402]
C251  2.2UF/NC  [SC0603]
C281  10UF  [SC0603]
C334  1UF  [SC0402]
C336  10NF/NC  [SC0402]
LB1  0  [SL0402]
LB12  LB  [SL0402]
LB14  0  [SL0603]
LB20  0  [SL0402]
LB31  0  [SL0402]
LB35  0  [SL0402]
R25  10K  [SR0402]
R32  12K  [SR0402]
R40  10K/NC  [SR0402]
R41  10K  [SR0402]
R42  1K  [SR0402]
R82  270  [SR0402]
R87  270  [SR0402]
S1  MSW2S5  [RSTSW5-R]
S2  MSW-6A  [SPSW6-T]
sheet SHEET_08
C11  1UF  [SC0603]
C20  10UF/NC  [SC0603]
C94  1UF  [SC0402]
C96  1UF  [SC0402]
C97  470NF  [SC0402]
C98  100NF/NC  [SC0402]
C99  100NF/NC  [SC0402]
C100  470NF/NC  [SC0402]
C101  100NF/NC  [SC0402]
C102  100NF  [SC0402]
C103  1UF/NC  [SC0402]
C104  100NF/NC  [SC0402]
C137  100NF/NC  [SC0402]
C264  10NF  [SC0402]
C270  10NF/NC  [SC0402]
LB7  0  [SL0603]
R18  0  [SR0402]
R35  0  [SR0402]
R36  0  [SR0402]
R37  0  [SR0402]
R38  10K/NC  [SR0402]
R45  240  [SR0402]
sheet SHEET_09
U1  S40V300_19X19  [TFBGA395-32-2323]  (sections A,B,C,D,E)

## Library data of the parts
ID1-ID6 = ID-BOARD: %195%%232%%202%%246%: PCB-MARK点ID-BOARD，亮铜直径40MIL，阻焊开窗直径80MIL，MARK点大小120MIL。; DEVICE: PCB_MARKPOINT_A
J4 J6 = SIP1_0: %195%%232%%202%%246%: 插针-普通方脚插针-1PIN-单排-直式-5.84MM-2.92MM-2.54MM-THT; %208%%161%%192%%224%%195%%251%%179%%198%: 插针; CODE: 14050101; DEVICE: TSW_101_23_F_S/NC
M20 M21 = HOLE: %195%%232%%202%%246%: 4.0MM铆钉，对应封装孔径162MIL(4.0MM铆接孔的禁布区为300MIL)金属化孔。; DEVICE: RIVET_HOLE162_R4_A
C2 C4 C25-C27 C111 C114 = C_1: %182%%238%%182%%168%%185%%164%%215%%247%%181%%231%%209%%185%(V): 25; %195%%232%%202%%246%: SMD陶瓷电容-25V-10000NF-+/-20%-X5R-0805; %208%%161%%192%%224%%195%%251%%179%%198%: SMD陶瓷电容; CODE: 8071629; COMPONENT_HIGH_MAX: 1.45MM; DEVICE: C2012X5R1E106KT000N1
C5 C8 C30 = C_1: %182%%238%%182%%168%%185%%164%%215%%247%%181%%231%%209%%185%(V): 6.3; %195%%232%%202%%246%: SMD陶瓷电容-6.3V-220NF-+/-10%-X5R-0402-BT; %208%%161%%192%%224%%195%%251%%179%%198%: SMD陶瓷电容; CODE: 8070584; COMPONENT_HIGH_MAX: 0.55MM; DEVICE: GRM155R60J224KE01D
C21 C58 = CP_4: %182%%238%%182%%168%%185%%164%%215%%247%%181%%231%%209%%185%(V): 16; %195%%232%%202%%246%: 非固体SMD铝电容-16V-100UF-+/-20%-6.3*5.4MM-极性-105DEGC-1000H-片式,温度敏感器件-工艺耐温250DEGC,5S; %208%%161%%192%%224%%195%%251%%179%%198%: 非固体SMD铝电容; CODE: 8010269; COMPONENT_HIGH_MAX: 5.7MM; DEVICE: UWT1C101MCL1GB
C22 = C_1: %182%%238%%182%%168%%185%%164%%215%%247%%181%%231%%209%%185%(V): 6.3; %195%%232%%202%%246%: SMD陶瓷电容-6.3V-47000NF-+/-20%-X5R-1206; %208%%161%%192%%224%%195%%251%%179%%198%: SMD陶瓷电容; CODE: 8070680; COMPONENT_HIGH_MAX: 1.9MM; DEVICE: CM316X5R476M06AT
C24 = C_1: %182%%238%%182%%168%%185%%164%%215%%247%%181%%231%%209%%185%(V): 50; %195%%232%%202%%246%: SMD陶瓷电容-50V-0.047NF-±5%-NP0-0402; %208%%161%%192%%224%%195%%251%%179%%198%: SMD陶瓷电容; CODE: 8070549; COMPONENT_HIGH_MAX: 0.55MM; DEVICE: C0402C470J5GAC_7867
C20 C35 C37 C39 C40 C90 C91 C110 C116 C281 = C_1: %182%%238%%182%%168%%185%%164%%215%%247%%181%%231%%209%%185%(V): 6.3; %195%%232%%202%%246%: SMD陶瓷电容-6.3V-10000NF-+/-20%-X5R-0603-BT,TS16949; %208%%161%%192%%224%%195%%251%%179%%198%: SMD陶瓷电容; CODE: 8070649; COMPONENT_HIGH_MAX: 0.9MM; DEVICE: C1608X5R0J106MT0A0E
C41 C43 C45 C46 C51 C53 C59 C67-C69 C112 = C_1: %182%%238%%182%%168%%185%%164%%215%%247%%181%%231%%209%%185%(V): 16; %195%%232%%202%%246%: SMD陶瓷电容-16V-100NF-±10%-X7R-0402; %208%%161%%192%%224%%195%%251%%179%%198%: SMD陶瓷电容; CODE: 8070614; COMPONENT_HIGH_MAX: 0.6MM; DEVICE: RMEMK105BJ104KV_FR
C44 = C_1: %182%%238%%182%%168%%185%%164%%215%%247%%181%%231%%209%%185%(V): 16; %195%%232%%202%%246%: SMD陶瓷电容-16V-10NF-+/-10%-X7R-0402; %208%%161%%192%%224%%195%%251%%179%%198%: SMD陶瓷电容; CODE: 8070449; COMPONENT_HIGH_MAX: 0.55MM; DEVICE: GRM155R71C103KA01D
C65 = C_1: %182%%238%%182%%168%%185%%164%%215%%247%%181%%231%%209%%185%(V): 10; %195%%232%%202%%246%: SMD陶瓷电容-10V-33NF-+/-10%-X7R-0402; %208%%161%%192%%224%%195%%251%%179%%198%: SMD陶瓷电容; CODE: 8070598; COMPONENT_HIGH_MAX: 0.55MM; DEVICE: C1005X7R1C333KT000F
C71 C72 = C_1: %182%%238%%182%%168%%185%%164%%215%%247%%181%%231%%209%%185%(V): 10; %195%%232%%202%%246%: SMD陶瓷电容-10V-2200NF-+/-10%-X5R-0603; %208%%161%%192%%224%%195%%251%%179%%198%: SMD陶瓷电容; CODE: 8070573; COMPONENT_HIGH_MAX: 0.9MM; DEVICE: GRM188R61A225KE34D
C76 C82 C84 = C_1: %182%%238%%182%%168%%185%%164%%215%%247%%181%%231%%209%%185%(V): 50; %195%%232%%202%%246%: SMD陶瓷电容-50V-0.022NF-+/-5%-NP0-0402-BT; %208%%161%%192%%224%%195%%251%%179%%198%: SMD陶瓷电容; CODE: 8070545; COMPONENT_HIGH_MAX: 0.55MM; DEVICE: RMUMK105CG220JV_F
C83 = C_1: %182%%238%%182%%168%%185%%164%%215%%247%%181%%231%%209%%185%(V): 50; %195%%232%%202%%246%: SMD陶瓷电容-50V-3.3NF-±10%-X7R-0402; %208%%161%%192%%224%%195%%251%%179%%198%: SMD陶瓷电容; CODE: 8070621; COMPONENT_HIGH_MAX: 0.55MM; DEVICE: GRM155R71H332KA01D
D2 = D_A_0: %195%%232%%202%%246%: 肖特基二极管-10V-3A-0.24V-SOD323-BT; %208%%161%%192%%224%%195%%251%%179%%198%: 肖特基二极管; CODE: 15010252; COMPONENT_HIGH_MAX: 1.1MM; DEVICE: IN4148/NC
J1 = PWC3_C_0: %195%%232%%202%%246%: IO连接器-DC JACK-3PIN-母座-3.9/1.3MM弯式-5V2A-00482858; CODE: 14240410; COMPONENT_HIGH_MAX: 11.25MM; DEVICE: DC_012_HW
J5 = SIP2_3: %195%%232%%202%%246%: 插针-普通方脚插针-2PIN-单排-直式-5.84MM-2.92MM-2.54MM-THT; %208%%161%%192%%224%%195%%251%%179%%198%: 插针; CODE: 14050028; COMPONENT_HIGH_MAX: 8.38MM; DEVICE: TSW_102_23_F_S
J10 = PWC3_C_0: %195%%232%%202%%246%: IO连接器-DC JACK-3PIN-母座-3.9/1.3MM弯式-5V2A-00482858; CODE: *; COMPONENT_HIGH_MAX: 11.25MM; DEVICE: DC_012_HW
L2 L4 = SWPA4020S3R3MT_3
L3 = SWPA4020S3R3MT_2
L5 = SWPA5040S6R8MT_1
R4 = R_6: %182%%238%%182%%168%%185%%166%%194%%202%(W): 0.06; %195%%232%%202%%246%: 片式厚膜电阻器-0.0625W-100000OHM-+/-5%-0402; %208%%161%%192%%224%%195%%251%%179%%198%: 片式厚膜电阻器; %215%%232%%214%%181%%212%%202%%208%%237%%198%%171%%178%%238%: +/-5%; CODE: 7090831; COMPONENT_HIGH_MAX: 0.4MM; DEVICE: RK73B1ELTP104J
R5 R47 R73 = R_6: %182%%238%%182%%168%%185%%166%%194%%202%(W): 0.06; %195%%232%%202%%246%: 片式厚膜电阻器-0.0625W-20000OHM-+/-1%-0402-TS16949; %208%%161%%192%%224%%195%%251%%179%%198%: 片式厚膜电阻器; %215%%232%%214%%181%%212%%202%%208%%237%%198%%171%%178%%238%: +/-1%; CODE: 7091374; COMPONENT_HIGH_MAX: 0.4MM; DEVICE: RC_02W2002FT
R6 = R_6: %182%%238%%182%%168%%185%%166%%194%%202%(W): 0.06; %195%%232%%202%%246%: 片式厚膜电阻器-0.0625W-47000OHM-+/-5%-0402-ELOM; %208%%161%%192%%224%%195%%251%%179%%198%: 片式厚膜电阻器; %215%%232%%214%%181%%212%%202%%208%%237%%198%%171%%178%%238%: +/-5%; CODE: 7090819; COMPONENT_HIGH_MAX: 0.4MM; DEVICE: RC0402JR_0747K
R7 R105 = R_6: %182%%238%%182%%168%%185%%166%%194%%202%(W): 0.06; %195%%232%%202%%246%: 片式厚膜电阻器-0.0625W-51000OHM-+/-1%-0402; %208%%161%%192%%224%%195%%251%%179%%198%: 片式厚膜电阻器; %215%%232%%214%%181%%212%%202%%208%%237%%198%%171%%178%%238%: +/-1%; CODE: 7091384; COMPONENT_HIGH_MAX: 0.4MM; DEVICE: RC_02W5102FT
R10 = R_6: %182%%238%%182%%168%%185%%166%%194%%202%(W): 0.06; %195%%232%%202%%246%: 片式厚膜电阻器-0.0625W-150000OHM-+/-1%-0402; %208%%161%%192%%224%%195%%251%%179%%198%: 片式厚膜电阻器; %215%%232%%214%%181%%212%%202%%208%%237%%198%%171%%178%%238%: +/-1%; CODE: 7090833; COMPONENT_HIGH_MAX: 0.4MM; DEVICE: RK73H1ELTP1503F
R13 = R_6: %182%%238%%182%%168%%185%%166%%194%%202%(W): 0.1; %195%%232%%202%%246%: 片式厚膜电阻器-0.1W-26100OHM-+/-1%-0603-BT; %208%%161%%192%%224%%195%%251%%179%%198%: 片式厚膜电阻器; %215%%232%%214%%181%%212%%202%%208%%237%%198%%171%%178%%238%: +/-1%; CODE: 7091991; COMPONENT_HIGH_MAX: 0.55MM; DEVICE: RK73H1JTTD2612F
R21 R23 = R_6: %182%%238%%182%%168%%185%%166%%194%%202%(W): 0.1; %195%%232%%202%%246%: 片式厚膜电阻器-0.1W-1000OHM-+/-1%-0603; %208%%161%%192%%224%%195%%251%%179%%198%: 片式厚膜电阻器; %215%%232%%214%%181%%212%%202%%208%%237%%198%%171%%178%%238%: +/-1%; CODE: 7092250; COMPONENT_HIGH_MAX: 0.5MM; DEVICE: RK73H1JTTD1001F
R52 R118 = R_6: %182%%238%%182%%168%%185%%166%%194%%202%(W): 0.06; %195%%232%%202%%246%: 片式厚膜电阻器-0.0625W-100000OHM-+/-5%-0402-BT; %208%%161%%192%%224%%195%%251%%179%%198%: 片式厚膜电阻器; %215%%232%%214%%181%%212%%202%%208%%237%%198%%171%%178%%238%: +/-5%; CODE: 7090831; COMPONENT_HIGH_MAX: 0.4MM; DEVICE: RK73B1ELTP104J
R53 R100 = R_6: %182%%238%%182%%168%%185%%166%%194%%202%(W): 0.06; %195%%232%%202%%246%: 片式厚膜电阻器-0.0625W-15000OHM-+/-1%-0402-BT; %208%%161%%192%%224%%195%%251%%179%%198%: 片式厚膜电阻器; %215%%232%%214%%181%%212%%202%%208%%237%%198%%171%%178%%238%: +/-1%; CODE: 7091372; COMPONENT_HIGH_MAX: 0.4MM; DEVICE: RC_02W1502FT
R70 = R_6: %182%%238%%182%%168%%185%%166%%194%%202%(W): 0.06; %195%%232%%202%%246%: 片式厚膜电阻器-0.0625W-33000OHM-+/-5%-0402; %208%%161%%192%%224%%195%%251%%179%%198%: 片式厚膜电阻器; %215%%232%%214%%181%%212%%202%%208%%237%%198%%171%%178%%238%: +/-5%; CODE: 7090828; COMPONENT_HIGH_MAX: 0.4MM; DEVICE: RK73B1ELTP333J
R81 = R_5: %182%%238%%182%%168%%185%%166%%194%%202%(W): 0.25; %195%%232%%202%%246%: 片式厚膜电阻器-0.25W-0OHM-<50MOHM-1206-2A-BT; %208%%161%%192%%224%%195%%251%%179%%198%: 片式厚膜电阻器; %215%%232%%214%%181%%212%%202%%208%%237%%198%%171%%178%%238%: <50MOHM; CODE: 7090002; COMPONENT_HIGH_MAX: 0.7MM; DEVICE: RC1206JR_070RL
R83 = R_6: %182%%238%%182%%168%%185%%166%%194%%202%(W): 0.13; %195%%232%%202%%246%: 片式厚膜电阻器-0.125W-2000OHM-+/-1%-0805; %208%%161%%192%%224%%195%%251%%179%%198%: 片式厚膜电阻器; %215%%232%%214%%181%%212%%202%%208%%237%%198%%171%%178%%238%: +/-1%; CODE: 7090225; COMPONENT_HIGH_MAX: 0.65MM; DEVICE: RK73H2ATTD2001F
R14 R95 = R_6: %182%%238%%182%%168%%185%%166%%194%%202%(W): 0.06; %195%%232%%202%%246%: 片式厚膜电阻器-0.0625W-0OHM-< 50MOHM-0402-1A-BT; %208%%161%%192%%224%%195%%251%%179%%198%: 片式厚膜电阻器; %215%%232%%214%%181%%212%%202%%208%%237%%198%%171%%178%%238%: < 50MOHM; CODE: 7090800; DEVICE: RC0402JR_070R
R99 = R_6: %182%%238%%182%%168%%185%%166%%194%%202%(W): 0.06; %195%%232%%202%%246%: 片式厚膜电阻器-0.0625W-11300OHM-+/-1%-0402; %208%%161%%192%%224%%195%%251%%179%%198%: 片式厚膜电阻器; %215%%232%%214%%181%%212%%202%%208%%237%%198%%171%%178%%238%: +/-1%; CODE: 7090816; COMPONENT_HIGH_MAX: 0.4MM; DEVICE: RC0402FR_0711K3
R101 = R_6: %182%%238%%182%%168%%185%%166%%194%%202%(W): 0.06; %195%%232%%202%%246%: 片式厚膜电阻器-0.0625W-24000OHM-+/-1%-0402; %208%%161%%192%%224%%195%%251%%179%%198%: 片式厚膜电阻器; %215%%232%%214%%181%%212%%202%%208%%237%%198%%171%%178%%238%: +/-1%; CODE: 7091376; COMPONENT_HIGH_MAX: 0.4MM; DEVICE: RC_02W2402FT
R102 = R_6: %182%%238%%182%%168%%185%%166%%194%%202%(W): 0.06; %195%%232%%202%%246%: 片式厚膜电阻器-0.0625W-180000OHM-+/-1%-0402; %208%%161%%192%%224%%195%%251%%179%%198%: 片式厚膜电阻器; %215%%232%%214%%181%%212%%202%%208%%237%%198%%171%%178%%238%: +/-1%; CODE: 7090823; COMPONENT_HIGH_MAX: 0.4MM; DEVICE: RC0402FR_07180KL
R104 = R_6: %182%%238%%182%%168%%185%%166%%194%%202%(W): 0.06; %195%%232%%202%%246%: 片式厚膜电阻器-0.0625W-2200OHM-+/-1%-0402; %208%%161%%192%%224%%195%%251%%179%%198%: 片式厚膜电阻器; %215%%232%%214%%181%%212%%202%%208%%237%%198%%171%%178%%238%: +/-1%; CODE: 7090810; COMPONENT_HIGH_MAX: 0.4MM; DEVICE: RC0402FR_072K2L
R110 = R_6: %182%%238%%182%%168%%185%%166%%194%%202%(W): 0.06; %195%%232%%202%%246%: 片式厚膜电阻器-0.0625W-75000OHM-+/-1%-0402; %208%%161%%192%%224%%195%%251%%179%%198%: 片式厚膜电阻器; %215%%232%%214%%181%%212%%202%%208%%237%%198%%171%%178%%238%: +/-1%; CODE: 7091008; COMPONENT_HIGH_MAX: 0.4MM; DEVICE: RK73H1ETTD7502F
U11 U13 = SY8032
U14 = MP1484_1
U15 = SY8009A: DEVICE: SY8089A_ETA3409
C6 = C_1: %182%%238%%182%%168%%185%%164%%215%%247%%181%%231%%209%%185%(V): 10; %195%%232%%202%%246%: SMD陶瓷电容-10V-220NF-+/-10%-X7R-0603-供电专用-供电专用; %208%%161%%192%%224%%195%%251%%179%%198%: SMD陶瓷电容; CODE: 8070856; COMPONENT_HIGH_MAX: 0.9MM; DEVICE: C0603C224K8RAC7867
Q4 = NPN-BEC_1: %195%%232%%202%%246%: 三极管-NPN-45V-100MA-225MW-200MV@100MA-SOT-23-180@2MA; %208%%161%%192%%224%%195%%251%%179%%198%: 三极管; CODE: 15050206; COMPONENT_HIGH_MAX: 1.26MM; DEVICE: BC847AE6327
Q13 Q14 = FETP-GSD_2: %195%%232%%202%%246%: MOSFET-P沟道--8V--3A-50MOHM--8V-SOT23; %208%%161%%192%%224%%195%%251%%179%%198%: MOSFET; CODE: 15060134; COMPONENT_HIGH_MAX: 1.11MM; DEVICE: IRLML6401TR
R98 = R_6: %182%%238%%182%%168%%185%%166%%194%%202%(W): 0.06; %195%%232%%202%%246%: 片式厚膜电阻器-0.0625W-10000OHM-±5%-0402; %208%%161%%192%%224%%195%%251%%179%%198%: 片式厚膜电阻器; %215%%232%%214%%181%%212%%202%%208%%237%%198%%171%%178%%238%: ±5%; CODE: 7090815; COMPONENT_HIGH_MAX: 0.4MM; DEVICE: RC_02W103JT
R144 = R_6: %182%%238%%182%%168%%185%%166%%194%%202%(W): 0.06; %195%%232%%202%%246%: 片式厚膜电阻器-0.0625W-4700OHM-+/-5%-0402-BT; %208%%161%%192%%224%%195%%251%%179%%198%: 片式厚膜电阻器; %215%%232%%214%%181%%212%%202%%208%%237%%198%%171%%178%%238%: +/-5%; CODE: 7090793; COMPONENT_HIGH_MAX: 0.4MM; DEVICE: RK73B1ELTP472J
C3 C7 C9-C11 C16 C18 C188 = C_1: %182%%238%%182%%168%%185%%164%%215%%247%%181%%231%%209%%185%(V): 25; %195%%232%%202%%246%: SMD陶瓷电容-25V-1000NF-+/-10%-X7R-0603; %208%%161%%192%%224%%195%%251%%179%%198%: SMD陶瓷电容; CODE: 8070962; COMPONENT_HIGH_MAX: 0.9MM; DEVICE: CETMK107B7105KA_T
C57 C74 C78 C85 C98 C99 C101 C102 C104 C119 C137 C194 = C_1: %182%%238%%182%%168%%185%%164%%215%%247%%181%%231%%209%%185%(V): 10; %195%%232%%202%%246%: SMD陶瓷电容-10V-100NF-+/-10%-X5R-0402; %208%%161%%192%%224%%195%%251%%179%%198%: SMD陶瓷电容; CODE: 8070561; COMPONENT_HIGH_MAX: 0.55MM; DEVICE: C0402C104K8PAC_7867
C248 C250 = C_1: %182%%238%%182%%168%%185%%164%%215%%247%%181%%231%%209%%185%(V): 6.3; %195%%232%%202%%246%: SMD陶瓷电容-6.3V-2200NF-+/-20%-X5R-0402-TS16949; %208%%161%%192%%224%%195%%251%%179%%198%: SMD陶瓷电容; CODE: 8070667; COMPONENT_HIGH_MAX: 0.6MM; DEVICE: GRM155R60J225ME15D
C364 C365 = C_1: %182%%238%%182%%168%%185%%164%%215%%247%%181%%231%%209%%185%(V): 50; %195%%232%%202%%246%: SMD陶瓷电容-50V-0.03NF-+/-5%-NPO-0402; %208%%161%%192%%224%%195%%251%%179%%198%: SMD陶瓷电容; CODE: 8070604; COMPONENT_HIGH_MAX: 0.55MM; DEVICE: GRM1555C1H300J
LB1 LB7 LB8 LB14 LB17 LB18 LB20 LB31 LB35 LB113 R18 R35-R37 = R_6: %182%%238%%182%%168%%185%%166%%194%%202%(W): 0.06; %195%%232%%202%%246%: 片式厚膜电阻器-0.0625W-0OHM-< 50MOHM-0402-1A-BT; %208%%161%%192%%224%%195%%251%%179%%198%: 片式厚膜电阻器; %215%%232%%214%%181%%212%%202%%208%%237%%198%%171%%178%%238%: < 50MOHM; CODE: 7090800; COMPONENT_HIGH_MAX: 0.4MM; DEVICE: RC0402JR_070R
R1 = R_6: %182%%238%%182%%168%%185%%166%%194%%202%(W): 0.1; %195%%232%%202%%246%: 片式厚膜电阻器-0.1W-1000000OHM-±5%-0603; %208%%161%%192%%224%%195%%251%%179%%198%: 片式厚膜电阻器; %215%%232%%214%%181%%212%%202%%208%%237%%198%%171%%178%%238%: ±5%; CODE: 7090263; DEVICE: RC0603JR_071M
R24 R82 R85 R87 = R_6: %182%%238%%182%%168%%185%%166%%194%%202%(W): 0.06; %195%%232%%202%%246%: 片式厚膜电阻器-0.0625W-270OHM-+/-5%-0402; %208%%161%%192%%224%%195%%251%%179%%198%: 片式厚膜电阻器; %215%%232%%214%%181%%212%%202%%208%%237%%198%%171%%178%%238%: +/-5%; CODE: 7090609; COMPONENT_HIGH_MAX: 0.4MM; DEVICE: RC0402JR_07270R
R25 R33 R38-R41 = R_6: %182%%238%%182%%168%%185%%166%%194%%202%(W): 0.06; %195%%232%%202%%246%: 片式厚膜电阻器-0.0625W-10000OHM-+/-5%-0402-BT; %208%%161%%192%%224%%195%%251%%179%%198%: 片式厚膜电阻器; %215%%232%%214%%181%%212%%202%%208%%237%%198%%171%%178%%238%: +/-5%; CODE: 7090815; COMPONENT_HIGH_MAX: 0.4MM; DEVICE: RC_02W103JT
R56 = R_6: %182%%238%%182%%168%%185%%166%%194%%202%(W): 0.06; %195%%232%%202%%246%: 片式厚膜电阻器-0.0625W-10000OHM-+/-5%-0402-BT; %208%%161%%192%%224%%195%%251%%179%%198%: 片式厚膜电阻器; %215%%232%%214%%181%%212%%202%%208%%237%%198%%171%%178%%238%: +/-5%; CODE: 7090815; DEVICE: RC_02W103JT
R61 = R_6: %182%%238%%182%%168%%185%%166%%194%%202%(W): 0.06; %195%%232%%202%%246%: 片式薄膜电阻器-0.0625W-200OHM-+/-0.1%-0402-+/-50PPM/DEGC; %208%%161%%192%%224%%195%%251%%179%%198%: 片式薄膜电阻器; %215%%232%%214%%181%%212%%202%%208%%237%%198%%171%%178%%238%: +/-0.1%; CODE: 7110054; COMPONENT_HIGH_MAX: 0.4MM; DEVICE: RN731ETTP2000B50
R68 = R: %182%%238%%182%%168%%185%%166%%194%%202%(W): 0.06; %195%%232%%202%%246%: 片式厚膜电阻器-0.0625W-75OHM-+/-1%-0402; %208%%161%%192%%224%%195%%251%%179%%198%: 片式厚膜电阻器; %215%%232%%214%%181%%212%%202%%208%%237%%198%%171%%178%%238%: +/-1%; CODE: 7091321; COMPONENT_HIGH_MAX: 0.4MM; DEVICE: RC_02W750FT
R42 R88 = R_6: %182%%238%%182%%168%%185%%166%%194%%202%(W): 0.06; %195%%232%%202%%246%: 片式厚膜电阻器-0.0625W-1000OHM-+/-5%-0402-BT; %208%%161%%192%%224%%195%%251%%179%%198%: 片式厚膜电阻器; %215%%232%%214%%181%%212%%202%%208%%237%%198%%171%%178%%238%: +/-5%; CODE: 7090809; COMPONENT_HIGH_MAX: 0.4MM; DEVICE: RC0402JR_071KL
R173 = R_6: %182%%238%%182%%168%%185%%166%%194%%202%(W): 0.06; %195%%232%%202%%246%: 片式厚膜电阻器-0.0625W-10000OHM-+/-1%-0402-BT; %208%%161%%192%%224%%195%%251%%179%%198%: 片式厚膜电阻器; %215%%232%%214%%181%%212%%202%%208%%237%%198%%171%%178%%238%: +/-1%; CODE: 7090867; COMPONENT_HIGH_MAX: 0.4MM; DEVICE: RK73H1ETTP1002F
X2 = X_B_1: %195%%232%%202%%246%: 晶体谐振器-24MHZ; %208%%161%%192%%224%%195%%251%%179%%198%: 晶体谐振器; CODE: 12020151; COMPONENT_HIGH_MAX: 1MM; DEVICE: E5SB400000F15D11
C34 C38 = C: %182%%238%%182%%168%%185%%164%%215%%247%%181%%231%%209%%185%(V): 10; %195%%232%%202%%246%: SMD陶瓷电容-10V-100NF-+/-10%-X5R-0402; %208%%161%%192%%224%%195%%251%%179%%198%: SMD陶瓷电容; CODE: 8070561; COMPONENT_HIGH_MAX: 0.55MM; DEVICE: C0402C104K8PAC_7867
C77 C94 C96 C103 C334 = C_1: %182%%238%%182%%168%%185%%164%%215%%247%%181%%231%%209%%185%(V): 10; %195%%232%%202%%246%: SMD陶瓷电容-10V-1000NF-+/-10%-X5R-0402-BT,TS16949; %208%%161%%192%%224%%195%%251%%179%%198%: SMD陶瓷电容; CODE: 8070612; COMPONENT_HIGH_MAX: 0.55MM; DEVICE: CV05X5R105K10AH
C164 C182 C264 C270 C336 = C_1: %182%%238%%182%%168%%185%%164%%215%%247%%181%%231%%209%%185%(V): 16; %195%%232%%202%%246%: SMD陶瓷电容-16V-10NF-+/-10%-X7R-0402-BT,TS16949; %208%%161%%192%%224%%195%%251%%179%%198%: SMD陶瓷电容; CODE: 8070449; COMPONENT_HIGH_MAX: 0.55MM; DEVICE: GRM155R71C103KA01D
C251 = C_1: %182%%238%%182%%168%%185%%164%%215%%247%%181%%231%%209%%185%(V): 6.3; %195%%232%%202%%246%: SMD陶瓷电容-6.3V-2200NF-+/-10%-X5R-0603-BT; %208%%161%%192%%224%%195%%251%%179%%198%: SMD陶瓷电容; CODE: 8070563; COMPONENT_HIGH_MAX: 0.95MM; DEVICE: CM105X5R225K06AT
LB12 = LB_5: %195%%232%%202%%246%: EMI磁珠-+/-25%-1000OHM-1.25OHM-0.25A-0402-1400OHM@1GHZ; %208%%161%%192%%224%%195%%251%%179%%198%: EMI磁珠; CODE: 10070019; COMPONENT_HIGH_MAX: 0.65MM; DEVICE: BLM15HG102SN1D
R32 = R_6: %182%%238%%182%%168%%185%%166%%194%%202%(W): 0.06; %195%%232%%202%%246%: 片式厚膜电阻器-0.0625W-12000OHM-+/-1%-0402; %208%%161%%192%%224%%195%%251%%179%%198%: 片式厚膜电阻器; %215%%232%%214%%181%%212%%202%%208%%237%%198%%171%%178%%238%: +/-1%; CODE: 7090817; DEVICE: RC0402FR_0712K
S1 = MSW2S5_0: %195%%232%%202%%246%: 微动开关-SPST-12VDC-0.05A0.4MM-3.5*2.9*1.55MM-终端专用-00822481; CODE: 16100071; COMPONENT_HIGH_MAX: 1.75MM; DEVICE: LS12T2_T
S2 = MSW-6A_0: %195%%232%%202%%246%: 微动开关-SPST-12VDC-0.05A-贴片-0.5MM-5.2*5.2*1.5MM-1,000,000; %208%%161%%192%%224%%195%%251%%179%%198%: 微动开关; COMPONENT_HIGH_MAX: 1.71MM; DEVICE: TMG_533_T_R
C97 C100 = C_1: %182%%238%%182%%168%%185%%164%%215%%247%%181%%231%%209%%185%(V): 6.3; %195%%232%%202%%246%: SMD陶瓷电容-6.3V-470NF-+/-10%-X5R-0402; %208%%161%%192%%224%%195%%251%%179%%198%: SMD陶瓷电容; CODE: 8070625; COMPONENT_HIGH_MAX: 0.55MM; DEVICE: GRM155R60J474KE19D
R45 = R_6: %182%%238%%182%%168%%185%%166%%194%%202%(W): 0.06; %195%%232%%202%%246%: 片式厚膜电阻器-0.0625W-240OHM-+/- 1%-0402-BT; %208%%161%%192%%224%%195%%251%%179%%198%: 片式厚膜电阻器; %215%%232%%214%%181%%212%%202%%208%%237%%198%%171%%178%%238%: +/- 1%; CODE: 7091782; COMPONENT_HIGH_MAX: 0.4MM; DEVICE: RC0402FR_07240RL
U1 = Hi3798MV100: DEVICE: Hi3798MV100_A

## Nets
1V1_CORE: C22.1(A) C37.1(A) C51.1(A) C82.2(B) C90.1(A) L3.2(B) LB12.2 LB31.1(A) LB113.1(A) R101.2(B) ; also on sheet 9
1V1_CPU: C21.1 C35.1(A) C41.1(A) C76.2(B) C116.1(A) L2.2(B) R53.2(B) ; also on sheet 9
1V5_DDR3: C20.1(A) C40.1(A) C68.1(A) C84.2(B) C94.1(A) C96.1(A) C97.1(A) C98.1(A) C99.1(A) C100.1(A) C101.1(A) C102.1(A) C103.1(A) C104.1(A) C110.1(A) C137.1(A) L4.2(B) R10.2(B) U1.J6(VDDIO_DDR_8) U1.J7(VDDIO_DDR_1) U1.K6(VDDIO_DDR_5) U1.K7(VDDIO_DDR_2) U1.L6(VDDIO_DDR_7) U1.N6(VDDIO_DDR_9) U1.P6(VDDIO_DDR_4) U1.T6(VDDIO_DDR_12) U1.T9(VDDIO_CK_DDR_1) U1.T10(VDDIO_CK_DDR_2) U1.U6(VDDIO_DDR_10) U1.U7(VDDIO_DDR_25) U1.V5(VDDIO_DDR_21) U1.V6(VDDIO_DDR_13) U1.V7(VDDIO_DDR_6) U1.V8(VDDIO_DDR_26) U1.V9(VDDIO_DDR_23) U1.V11(VDDIO_DDR_24) U1.V12(VDDIO_DDR_3) U1.V13(VDDIO_DDR_11) U1.V14(VDDIO_DDR_22) U1.W4(VDDIO_DDR_20) U1.W5(VDDIO_DDR_19) U1.W6(VDDIO_DDR_18) U1.W7(VDDIO_DDR_17) U1.Y4(VDDIO_DDR_16) U1.Y5(VDDIO_DDR_15) U1.Y6(VDDIO_DDR_14) ; also on sheet 11 12
3V3: C2.1(A) C4.1(A) C25.1(A) C26.1(A) C27.1(A) C39.1(A) C46.1(A) C53.1(A) C67.1(A) C69.1(A) C91.1(A) C114.1(A) L5.2(B) Q13.2(S) R6.1(A) R83.1(A) R88.2(B) R105.2(B) U11.4(VIN) U13.4(VIN) U15.4(VIN) ; also on sheet 9 15 17
3V3_MOS: C74.1(A) LB1.2(B) LB7.2(B) LB8.2(B) LB14.1(A) LB17.2(B) LB18.1(A) LB20.1(A) LB35.1(A) Q13.3(D) R25.1(A) R41.2(B) U1.M19(DVDD3318_NF_2) U1.N19(DVDD3318_NF_1) ; also on sheet 9 13 14 17 18 19
5V0: C6.1(A) C58.1 C59.1(A) C111.1(A) C112.1(A) D2.2(A) J5.1(A1) Q14.2(S) R4.1(A) R81.2(B) R144.1(A) U14.2(IN)
5V0_MOS: Q14.3(D) ; also on sheet 14 16 19
AVDD11_USB3: C16.1(A) C119.1(A) LB113.2(B) U1.R16(DVDD11_USB3) U1.R17(AVDD11_VP_USB3) U1.T17(AVDD11_VPTX0_USB3)
AVDD33_ADAC: C188.1(A) C194.1(A) LB35.2(B) R39.2(B) U1.E19(AVDD33_ADAC)
AVDD33_USB2: C3.1(A) LB17.1(A) U1.K19(AVDD33_USB2)
AVDD33_USB3: C18.1(A) LB18.2(B) U1.W17(AVDD33_USB3_1) U1.W18(AVDD33_USB3_2)
GND: C2.2(B) C3.2(B) C4.2(B) C5.2(B) C7.2(B) C8.2(B) C9.2(B) C10.2(B) C11.2(B) C16.2(B) C18.2(B) C20.2(B) C21.2 C22.2(B) C24.2(B) C25.2(B) C26.2(B) C27.2(B) C30.2(B) C34.2(B) C35.2(B) C37.2(B) C38.1(A) C39.2(B) C40.2(B) C41.2(B) C43.2(B) C44.2(B) C45.2(B) C46.2(B) C51.2(B) C53.2(B) C57.2(B) C58.2 C59.2(B) C67.2(B) C68.2(B) C69.2(B) C71.2(B) C72.2(B) C74.2(B) C77.2(B) C78.2(B) C85.2(B) C90.2(B) C91.2(B) C94.2(B) C96.2(B) C97.2(B) C98.2(B) C99.2(B) C100.2(B) C101.2(B) C102.2(B) C103.2(B) C104.2(B) C110.2(B) C111.2(B) C112.2(B) C114.2(B) C116.2(B) C119.2(B) C137.2(B) C164.2(B) C182.2(B) C188.2(B) C194.2(B) C248.2(B) C250.1(A) C251.2(B) C264.2(B) C270.2(B) C281.2(B) C334.2(B) C336.2(B) C364.2(B) C365.2(B) J1.2(A2) J1.3(A3) J4.1 J6.1 J10.2(A2) J10.3(A3) Q4.2(E) R13.1(A) R24.2(B) R32.1(A) R33.2(B) R38.1(A) R40.2(B) R45.2(B) R52.2(B) R56.1(A) R61.1(A) R82.1(A) R83.2(B) R85.2(B) R87.1(A) R99.1(A) R100.2(B) R104.2(B) R173.2(B) S1.1(P1) S1.3(S1) S1.4(S2) S1.5(S3) S1.6(S4) S1.7(S5) S2.3 S2.4 S2.5 S2.6 U1.A3(AVSS_FE_4) U1.A23(AVSS_ADAC_5) U1.B3(AVSS_FE_2) U1.B8(AVSS_USB1_2) U1.B23(AVSS_ADAC_4) U1.C4(AVSS_FE_3) U1.C6(AVSS_USB0) U1.C8(AVSS_USB1_1) U1.C15(AVSS_HDMITX_1) U1.C17(AVSS_HDMITX_2) U1.C21(AVSS_ADAC_2) U1.C22(AVSS_ADAC_3) U1.D4(AVSS_FE_1) U1.D6(AVSS_USB2_3) U1.D14(AVSS_HDMITX_5) U1.D15(AVSS_HDMITX_3) U1.D17(AVSS_HDMITX_4) U1.D20(AVSS_ADAC_1) U1.D21(AVSS_VDAC_1) U1.D22(AVSS_VDAC_5) U1.E16(AVSS_HDMITX_7) U1.E17(AVSS_HDMITX_6) U1.E21(AVSS_VDAC_2) U1.E22(AVSS_VDAC_3) U1.F21(AVSS_VDAC_4) U1.G20(AVSS_VDAC_6) U1.L20(AVSS_USB2_1) U1.L21(AVSS_USB2_2) U11.2(GND) U13.2(GND) U14.4(GND1) U14.9(GND2) U15.2(GND) X2.2(GND1) X2.4(GND2) ; also on sheet 9 10 11 12 13 14 15 16 17 18 19
ADAC_VOUTL: U1.B22(ADAC_VOUTL) ; also on sheet 16
ADAC_VOUTR: U1.A22(ADAC_VOUTR) ; also on sheet 16
CORE_CTRL: R23.2(B) U1.H22(GPIO2_6/I2C2_SCL/PMC_PWM0)
CPU_CTRL: R21.2(B) U1.H23(GPIO2_7/I2C2_SDA/PMC_PWM1)
CVBS: U1.E23(VDAC) ; also on sheet 18
DDR_ADDR0: U1.AC14(DDR3_A0) ; also on sheet 11 12
DDR_ADDR1: U1.Y10(DDR3_A1) ; also on sheet 11 12
DDR_ADDR2: U1.W14(DDR3_A2) ; also on sheet 11 12
DDR_ADDR3: U1.AB14(DDR3_A3) ; also on sheet 11 12
DDR_ADDR4: U1.W10(DDR3_A4) ; also on sheet 11 12
DDR_ADDR5: U1.Y16(DDR3_A5) ; also on sheet 11 12
DDR_ADDR6: U1.AA10(DDR3_A6) ; also on sheet 11 12
DDR_ADDR7: U1.AA16(DDR3_A7) ; also on sheet 11 12
DDR_ADDR8: U1.AB11(DDR3_A8) ; also on sheet 11 12
DDR_ADDR9: U1.AA12(DDR3_A9) ; also on sheet 11 12
DDR_ADDR10: U1.Y8(DDR3_A10) ; also on sheet 11 12
DDR_ADDR11: U1.Y11(DDR3_A11) ; also on sheet 11 12
DDR_ADDR12: U1.AB9(DDR3_A12) ; also on sheet 11 12
DDR_ADDR13: U1.Y15(DDR3_A13) ; also on sheet 11 12
DDR_ADDR14: U1.AA11(DDR3_A14) ; also on sheet 11 12
DDR_ADDR15: U1.W12(DDR3_A15) ; also on sheet 11 12
DDR_BA0: U1.AC15(DDR3_BA0) ; also on sheet 11 12
DDR_BA1: U1.AA9(DDR3_BA1) ; also on sheet 11 12
DDR_BA2: U1.Y12(DDR3_BA2) ; also on sheet 11 12
DDR_CASN: U1.Y14(DDR3_CAS_N) ; also on sheet 11 12
DDR_CKE: R38.2(B) U1.W9(DDR3_CKE) ; also on sheet 11 12
DDR_CLK0N: R35.1(A) ; also on sheet 11
DDR_CLK0P: R18.1(A) ; also on sheet 11
DDR_CLK1N: R37.1(A) ; also on sheet 12
DDR_CLK1P: R36.1(A) ; also on sheet 12
DDR_CSN: U1.AC12(DDR3_CS_N_0) ; also on sheet 11 12
DDR_DM0: U1.K4(DDR3_DM0) ; also on sheet 11
DDR_DM1: U1.L5(DDR3_DM1) ; also on sheet 11
DDR_DM2: U1.AA1(DDR3_DM2) ; also on sheet 12
DDR_DM3: U1.Y2(DDR3_DM3) ; also on sheet 12
DDR_DQ0: U1.H4(DDR3_DQ0) ; also on sheet 11
DDR_DQ1: U1.N1(DDR3_DQ1) ; also on sheet 11
DDR_DQ2: U1.H1(DDR3_DQ2) ; also on sheet 11
DDR_DQ3: U1.P3(DDR3_DQ3) ; also on sheet 11
DDR_DQ4: U1.H5(DDR3_DQ4) ; also on sheet 11
DDR_DQ5: U1.R3(DDR3_DQ5) ; also on sheet 11
DDR_DQ6: U1.H2(DDR3_DQ6) ; also on sheet 11
DDR_DQ7: U1.P2(DDR3_DQ7) ; also on sheet 11
DDR_DQ8: U1.M4(DDR3_DQ8) ; also on sheet 11
DDR_DQ9: U1.K2(DDR3_DQ9) ; also on sheet 11
DDR_DQ10: U1.M5(DDR3_DQ10) ; also on sheet 11
DDR_DQ11: U1.J3(DDR3_DQ11) ; also on sheet 11
DDR_DQ12: U1.N4(DDR3_DQ12) ; also on sheet 11
DDR_DQ13: U1.J4(DDR3_DQ13) ; also on sheet 11
DDR_DQ14: U1.P4(DDR3_DQ14) ; also on sheet 11
DDR_DQ15: U1.J5(DDR3_DQ15) ; also on sheet 11
DDR_DQ16: U1.T5(DDR3_DQ16) ; also on sheet 12
DDR_DQ17: U1.AA5(DDR3_DQ17) ; also on sheet 12
DDR_DQ18: U1.T2(DDR3_DQ18) ; also on sheet 12
DDR_DQ19: U1.AB5(DDR3_DQ19) ; also on sheet 12
DDR_DQ20: U1.R5(DDR3_DQ20) ; also on sheet 12
DDR_DQ21: U1.AC6(DDR3_DQ21) ; also on sheet 12
DDR_DQ22: U1.T3(DDR3_DQ22) ; also on sheet 12
DDR_DQ23: U1.AA6(DDR3_DQ23) ; also on sheet 12
DDR_DQ24: U1.AA4(DDR3_DQ24) ; also on sheet 12
DDR_DQ25: U1.U1(DDR3_DQ25) ; also on sheet 12
DDR_DQ26: U1.AB3(DDR3_DQ26) ; also on sheet 12
DDR_DQ27: U1.U3(DDR3_DQ27) ; also on sheet 12
DDR_DQ28: U1.AC2(DDR3_DQ28) ; also on sheet 12
DDR_DQ29: U1.T4(DDR3_DQ29) ; also on sheet 12
DDR_DQ30: U1.AB2(DDR3_DQ30) ; also on sheet 12
DDR_DQ31: U1.U4(DDR3_DQ31) ; also on sheet 12
DDR_DQS0N: U1.L1(DDR3_DQS0_N) ; also on sheet 11
DDR_DQS0P: U1.L2(DDR3_DQS0_P) ; also on sheet 11
DDR_DQS1N: U1.M3(DDR3_DQS1_N) ; also on sheet 11
DDR_DQS1P: U1.M2(DDR3_DQS1_P) ; also on sheet 11
DDR_DQS2N: U1.V2(DDR3_DQS2_N) ; also on sheet 12
DDR_DQS2P: U1.V3(DDR3_DQS2_P) ; also on sheet 12
DDR_DQS3N: U1.W2(DDR3_DQS3_N) ; also on sheet 12
DDR_DQS3P: U1.W1(DDR3_DQS3_P) ; also on sheet 12
DDR_ODT: U1.AB15(DDR3_ODT_0) ; also on sheet 11 12
DDR_PLL: C11.1(A) C264.1(A) C270.1(A) LB7.1(A) U1.N8(AVDD_DDRPLL1) U1.T12(AVDD_DDRPLL2)
DDR_RASN: U1.AB16(DDR3_RAS_N) ; also on sheet 11 12
DDR_RESETN: U1.AB13(DDR3_RESET_N) ; also on sheet 11 12
DDR_WEN: U1.Y13(DDR3_WE_N) ; also on sheet 11 12
FE_1V1: C248.1(A) U1.G10(AVDD11_FE)
FE_3V3: C7.1(A) LB8.1(A) U1.E5(AVDD33_FE)
HDMI_TX0N: U1.D16(HDMI_TX0N) ; also on sheet 19
HDMI_TX0P: U1.C16(HDMI_TX0P) ; also on sheet 19
HDMI_TX1N: U1.B15(HDMI_TX1N) ; also on sheet 19
HDMI_TX1P: U1.A15(HDMI_TX1P) ; also on sheet 19
HDMI_TX2N: U1.C14(HDMI_TX2N) ; also on sheet 19
HDMI_TX2P: U1.B14(HDMI_TX2P) ; also on sheet 19
HDMI_TX_1V1: C78.1(A) C164.1(A) C251.1(A) C281.1(A) LB12.1 U1.G14(AVCC11_HDMITX_1) U1.G15(AVCC11_HDMITX_2)
HDMI_TX_3V3: C57.1(A) C77.1(A) LB1.1(A) U1.E15(AVCC33_HDMITX)
HDMI_TX_CEC: U1.C18(GPIO4_7/HDMITX_CEC) ; also on sheet 19
HDMI_TX_HOTPLUG: U1.B19(GPIO4_6/HDMITX_HOTPLUG) ; also on sheet 19
HDMI_TX_SCL: U1.D18(GPIO4_5/HDMITX_SCL) ; also on sheet 19
HDMI_TX_SDA: U1.A19(GPIO4_4/HDMITX_SDA) ; also on sheet 19
HDMI_TXCN: U1.B17(HDMI_TXCN) ; also on sheet 19
HDMI_TXCP: U1.A17(HDMI_TXCP) ; also on sheet 19
IR_IN: U1.Y21(GPIO5_1/IR_IN) ; also on sheet 15
LED0_BASE: U1.B2(GPIO2_2/FE_LED_BASE) ; also on sheet 17
LED0_LINK_ACT: U1.B1(GPIO2_1/FE_LED_ACT) ; also on sheet 17
LED_GREEN: U1.AB22(GPIO5_5/LED_DATA) ; also on sheet 15
LED_RED: U1.AC22(GPIO5_6/LED_CLK) ; also on sheet 15
MUTE_CTRL: U1.C19(MUTE_CTRL/GPIO4_3) ; also on sheet 16
NF_ALE_EMMC_PWREN: U1.N20(NF_ALE/SDIO1_CARD_POWER_EN/GPIO0_1) ; also on sheet 13
NF_CLE: U1.N21(NF_CLE/SDIO1_CWPR/GPIO0_2) ; also on sheet 13
NF_CSN0_EMMC_CMD: U1.N22(NF_CSN0/SDIO1_CCMD) ; also on sheet 13
NF_DQ0_EMMC_D0: U1.R23(EBI_DQ0/SDIO1_CDATA0) ; also on sheet 13
NF_DQ1_EMMC_D1: U1.R22(EBI_DQ1/SDIO1_CDATA1) ; also on sheet 13
NF_DQ2_EMMC_D2: U1.R21(EBI_DQ2/SDIO1_CDATA2) ; also on sheet 13
NF_DQ3_EMMC_D3: U1.T21(EBI_DQ3/SDIO1_CDATA3) ; also on sheet 13
NF_DQ4_EMMC_D4: U1.T20(EBI_DQ4/SDIO1_CDATA4) ; also on sheet 13
NF_DQ5_EMMC_D5: U1.U22(EBI_DQ5/SDIO1_CDATA5) ; also on sheet 13
NF_DQ6_EMMC_D6: U1.U23(EBI_DQ6/SDIO1_CDATA6) ; also on sheet 13
NF_DQ7_EMMC_D7_BOOT_SEL0: R33.1(A) U1.U21(EBI_DQ7/SDIO1_CDATA7/BOOT_SEL0) ; also on sheet 13
NF_RDY0_EMMC_RST: U1.M21(NF_RDY0/SDIO1_RST) ; also on sheet 13
NF_REN_EMMC_CLK: R68.1(A) ; also on sheet 13
NF_WEN_EMMC_DET: R56.2(B) U1.P21(NF_WEN/SDIO1_CARD_DETECT/GPIO0_0) ; also on sheet 13
PWR_OFF/ON: R40.1(A) R41.1(A) U1.J23(JTAG_TDI/GPIO0_7)
RECOVERY: C38.2(B) R25.2(B) S1.2(P2) U1.J22(JTAG_TDO/GPIO2_0)
RX+_PHY0: U1.D5(FE_RXP) ; also on sheet 17
RX-_PHY0: U1.C5(FE_RXN) ; also on sheet 17
SPDIF_OUT_BOOT_SEL1: R39.1(A) U1.A20(SPDIF_OUT/GPIO4_2/BOOT_SEL1)
STANDBY_PWROFF: R5.1(A) R47.1(A) R73.1(A) R88.1(A) R98.1(A) U1.AB23(GPIO5_0/STANDBY_PWROFF)
TX+_PHY0: U1.B4(FE_TXP) ; also on sheet 17
TX-_PHY0: U1.A4(FE_TXN) ; also on sheet 17
UART0_RXD: U1.AA22(UART0_RXD/UART1_RXD) ; also on sheet 17
UART0_TXD: U1.AA23(UART0_TXD/UART1_TXD) ; also on sheet 17
USB0_DM: U1.A6(USB0_DM) ; also on sheet 14
USB0_DP: U1.B6(USB0_DP) ; also on sheet 14
USB01_1V1: C334.1(A) C336.1(A) LB31.2(B) U1.G11(AVCC11_USB01)
USB01_3V3: C10.1(A) C182.1(A) LB20.2(B) U1.D7(AVDD33_USB01)
USB1_DM: U1.B7(USB1_DM) ; also on sheet 14
USB1_DP: U1.C7(USB1_DP) ; also on sheet 14
USB3_DM: U1.AC18(USB3_DM) ; also on sheet 14
USB3_DP: U1.AB18(USB3_DP) ; also on sheet 14
USB3_RXN: U1.AB20(USB3_RXN) ; also on sheet 14
USB3_RXP: U1.AC20(USB3_RXP) ; also on sheet 14
USB3_TXN: U1.AA19(USB3_TXN) ; also on sheet 14
USB3_TXP: U1.Y19(USB3_TXP) ; also on sheet 14
USB_BOOT: R42.2(B) U1.H21(USB_BOOT/GPIO2_5)
VDAC_3V3: C9.1(A) C85.1(A) LB14.2(B) U1.E20(AVDD33_VDAC_1) U1.F19(AVDD33_VDAC_2) U1.G19(AVDD33_VDAC_3)
XIN: C364.1(A) R1.2(B) U1.W23(XIN) X2.1
XOUT: R1.1(A) R14.1(A) U1.W22(XOUT)
N11825: R37.2(B) U1.AB7(DDR3_CLK1_N)
N11829: R36.2(B) U1.AA7(DDR3_CLK1_P)
N11833: R35.2(B) U1.AB8(DDR3_CLK0_N)
N11837: R18.2(B) U1.AC8(DDR3_CLK0_P)
N13018: C34.1(A) R42.1(A) S2.1 S2.2
N13348: R82.2(B) R87.2(B) U1.D8(USB01_REXT)
N13354: C250.2(B) U1.G17(ADAC_VREFDAC)
N13392: R32.2(B) U1.F20(VDAC_IREF)
N14505: C365.1(A) R14.2(B) X2.3
N14551: R173.1(A) U1.E6(FE_REXT)
N14559: R24.1(A) R85.1(A) U1.L19(USB2_REXT)
N14577: R61.2(B) U1.Y17(USB3_REXT)
N14993: C6.2(B) Q13.1(G) Q14.1(G) R118.1(A)
N15011: Q4.1(B) R98.2(B)
N15047: Q4.3(C) R118.2(B) R144.2(B)
N16339: C76.1(A) R53.1(A) R70.1(A) R99.2(B) U11.6(FB)
N16359: C8.1(A) R73.2(B) U11.1(EN)
N16369: L3.1(A) U13.3(LX)
N16373: R102.1(A) R110.2(B)
N16377: C45.1(A) C72.1(A) R23.1(A) R102.2(B)
N16389: C82.1(A) R13.2(B) R101.1(A) R110.1(A) U13.6(FB)
N16409: L2.1(A) U11.3(LX)
N16413: C43.1(A) C71.1(A) R7.2(B) R21.1(A)
N16425: L4.1(A) U15.3(LX)
N16429: C84.1(A) R10.1(A) R52.1(A) U15.5(FB)
N16469: C5.1(A) R5.2(B) U13.1(EN)
N16479: R7.1(A) R70.2(B)
N16483: C65.2(B) L5.1(A) U14.3(SW)
N16493: C65.1(A) R95.2(B)
N16503: R4.2(B) U14.7(EN)
N16509: C24.1(A) C83.1(A) U14.6(COMP/NC)
N16519: C83.2(B) R104.1(A)
N16523: D2.1(K) R95.1(A) U14.1(BS)
N16529: R100.1(A) R105.1(A) U14.5(FB)
N16537: C30.1(A) R6.2(B) R47.2(B) U15.1(EN)
N16583: J1.1(A1) J5.2(A2) J10.1(A1) R81.1(A)
N714369: C44.1(A) U14.8(SS)
N1052664: R45.1(A) U1.W16(DDR3_ZQ)
N6339054: R68.2(B) U1.N23(NF_REN/SDIO1_CCLK_OUT)

Not connected (* = marked no-connect by the designer): ID1 1*; ID2 1*; ID3 1*; ID4 1*; ID5 1*; ID6 1*; M20 1(GND)*; M21 1(GND)*; U1 A8(GPIO6_7/I2S0_DIN0) A9(GPIO6_5/I2S0_DOUT0) A11(GPIO6_1/SPI_CSN1) A12(GPIO4_1/I2C1_SCL/UART2_TXD/SPI_SDI) AA21(GPIO5_2/LED_CSN0)* B9(GPIO6_6/I2S0_MCLK) B11(GPIO6_0/I2C1_SDA/UART2_RTSN/SPI_CSN0) B12(GPIO4_0/UART2_RXD/SPI_SDO) C1(SDIO0_CWPR/GPIO2_3) C2(SDIO0_CDATA1/GPIO3_0) C9(GPIO6_4/I2S0_WS) C10(GPIO6_3/I2S0_BCLK) C11(GPIO6_2/SLIC_RST) C12(GPIO0_3/UART2_CTSN/SPI_SCLK) D3(SDIO0_CDATA0/GPIO3_1) E1(SDIO0_CDATA3/GPIO3_4) E2(SDIO0_CCMD/GPIO3_3) E3(SDIO0_CCLK_OUT/GPIO3_2) F1(SDIO0_CARD_DETECT/GPIO3_6) F2(SDIO0_CDATA2/GPIO3_5) F3(SDIO0_CARD_POWER_EN/GPIO3_7) G5(CAPACITOR_LDO) G21(JTAG_SEL)* J21(JTAG_TCK/GPIO0_6)* K20(JTAG_TRSTN/GPIO0_5)* K21(JTAG_TMS/GPIO0_4)* L22(USB2_DM) L23(USB2_DP) Y22(FUNC_SEL)*; U11 5(PG)*; U13 5(PG)*

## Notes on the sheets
sheet 1
- PAGE1
- Title Page
- PAGE2
- Power Tree
- PAGE3
- Block Diagram
- PAGE4
- Power on board
- PAGE5
- Power Ctrl
- PAGE6
- Unit 1 of Hi3798M(NAND/USB3.0/IR/SDIO/XTAL/FE)
- PAGE7
- Unit 2 of Hi3798M(JTAG/USB2.0/HDMI TX/DAC/I2S/SPI/UART)
- PAGE8
- Unit 3 of Hi3798M(DDR3)
- PAGE9
- Unit 4 of Hi3798M(POWER)
- PAGE10
- Unit 5 of Hi3798M(VSS)
- Hi3798MDMO1C
- PAGE11
- DDRA
- PAGE12
- DDRB
- PAGE13
- NAND FLASH/EMMC
- PAGE14
- USB2.0/USB3.0/WIFI
- VER_E_V1.0.0.0
- PAGE15
- SD CARD/IR
- PAGE16
- Audio Output
- PAGE17
- FE PHY/UART
- PAGE18
- VDAC OUTPUT
- Hi3798MV100 DEMO Board
- PAGE19
- HDMI TX
- PAGE20
- UART Board
- 2 layers PCB with 2 DDR3 16bit
- Board Size:124mm x 80mm x 1.6mm
sheet 2
- Power Tree
- 5V0_MOS
- 1000mA
- AUDIO AMP
- PMOS
- HDMI
- 5V
- 5V_VBUS
- USB x 2
- SW x 2
- 3V3
- MAX 2600mA
- 3V3 Standby
- DCDC
- 20mA
- IR & LED
- CHIP
- PMOS
- 3V3_MOS
- 170mA
- I/O
- USB
- VDAC
- NAND FLASH/eMMC
- ADAC
- FE
- HDMI
- 1V1_CORE
- PLL
- 612mA(MAX 2300mA)
- CORE
- DCDC
- USB
- 1V1_CPU
- VDAC
- 303mA(MAX 2560mA)
- CPU
- HDMI
- DCDC
- FE
- PLL
- 1V5_DDR3
- DCDC
- 421mA(MAX 1000mA)
- DDR PHY
- DDR
sheet 3
- Block Diagram
- 5V0
- HDMI
- ETH
- USB2.0
- KEY
- USB3.0
- L/R/CVBS
- DDRA
- Hi3798MV100
- DDRB
- WIFI
- IR/LED/KEY
sheet 4
- 5V PLUG-IN
- CPU POWER
- Vcpu=0.92V-1.5V
- 3A
- SWPA4020S3R3MT
- 1%
- SY8032
- 1%
- 1%
- 1%
- 1%
- 3.3V POWER
- MP1484 3A
- 3A
- SWPA5040S6R6MT
- 0.925V
- 1%
- CORE POWER
- 1%
- Vcore=0.9V-1.32V
- 3A
- SWPA4020S3R3MT
- 1%
- MP1484_ETA1486
- ETA1486 4A
- VOUT=0.923*(1+26.1K/10K)=3.33V
- C44=100nF;C65=10nF;R104=5.6K;C83=3.3nF;C24=NC
- SY8032
- R105=26.1K;R100=10K
- 1%
- 1%
- 1%
- MP1484 3A
- 1%
- VOUT=0.925*(1+26.1K/10K)=3.34V
- C44=100nF;C65=10nF;R104=5.6K;C83=3.3nF;C24=NC;R105=26.1K;R100=10K
- DDR POWER
- Vo=0.6x(1+Rup/Rdown)=1.5V
- 2A
- SWPA4020S3R3MT
- 1%
- 1%
sheet 5
- Power Ctrl
- IRLML6401TR
- IRLML6401TR
- BC847AE6327
- STANDBY_PWROFF
- 0
- Power Off
- 1
- Power On
sheet 6
- Unit 1 of Hi3798MV100(NAND/USB3.0/IR/SDIO/XTAL/FE)
- 1%
- 2 Layers
- R68=33ohm
- Close to Hi3798M
- 1%
- 135ohm
- 1%
- BOOT DEVICE SEL
- BOOT_SEL[1:0]
- BOOT_SEL1
- PD
- 11:eMMC
- System Oscillator
- 01:NAND Flash
- BOOT_SEL0
- PU
- 10:fSD
- PD
- PU
- ** FE PHY Design guideline **
- A.routing
- 1.Route as 100 Ohm differential impedance.
- 2.Differential pairs should be routed on TOP layer only.
- 3.Differential pairs should be separated from other traces by GND .
- B.trace length
- 1.The length for the differential pairs should be less than 5 inches.
- 2.Match trace length of RX and TX differential pairs, 10 mils max within a pair.
- C.component selection
- 1.REXT resistor should be 10K ohm +/-1%.
- 2.ESD components are suggested for ports protection,
- Put between Hi398MV100 and transformer.
sheet 7
- Unit 2 of Hi3798MV100(JTAG/USB2.0/HDMI TX/DAC/I2S/SPI/UART)
- ** Audio & Video Design guideline **
- A.VIDEO
- 1.VIDEO REXT resistor should be 12K +/-1% precision.
- 1%
- 2.REXT/COMP should be traced as short as possible,
- and isolated from all other traces.
- B.AUDIO
- 1.VREF should be traced as short as possible,
- and isolated from all other traces.
- BLM15HG102SN1D
- PU
- NOTE:EMI-1000ohm or 600ohm@100MHz
- PD
- PD
- PU
- R40=NC,R41=10k:power up-->start
- R40=10k,R41=NC:power up-->pull key-->start
- TMG_533_T_R
- 135ohm
- 1%
- USB0:usb_boot/adb
- ** USB Design guideline **
- A.routing
- 1.Route as 90 Ohm differential impedance.
- 2.Differential pairs should be routed on TOP layer only.
- 3.Differential pairs should be separated from other traces by GND .
- B.trace length
- 1.The length for the differential pairs should be less than 5 inches.
- 2.Match trace length of DP and DM differential pairs, 10 mils max within a pair.
- C.component selection
- 1.USB2.0 REXT resistor should be 135 ohm +/-1% and USB3.0 200 ohm +/-1%.
- 2.ESD components are suggested for ports protection.
- 3.Equivalent capacitance of ESD component should be < 1.5pF.
sheet 8
- Unit 3 of Hi3798MV100(DDR)
- 1%
- Close to Hi3798MV100
- ** DDR Design guideline **
- A.general suggestion
- 1.Hi3798MV100 supports up to 2GB DDR3.
- 2.DDR chip and DDR controller both need at least one 10uF decoupling ceramic capacitor.
- 3.The ciruit of DDR_VREF_CA and DDR_VREF_DQ must be independent
- 4. 3V3 DDRPLL is needed.
- B.Layout suggestion
- 1. Please copy hisilicon demo board completely
